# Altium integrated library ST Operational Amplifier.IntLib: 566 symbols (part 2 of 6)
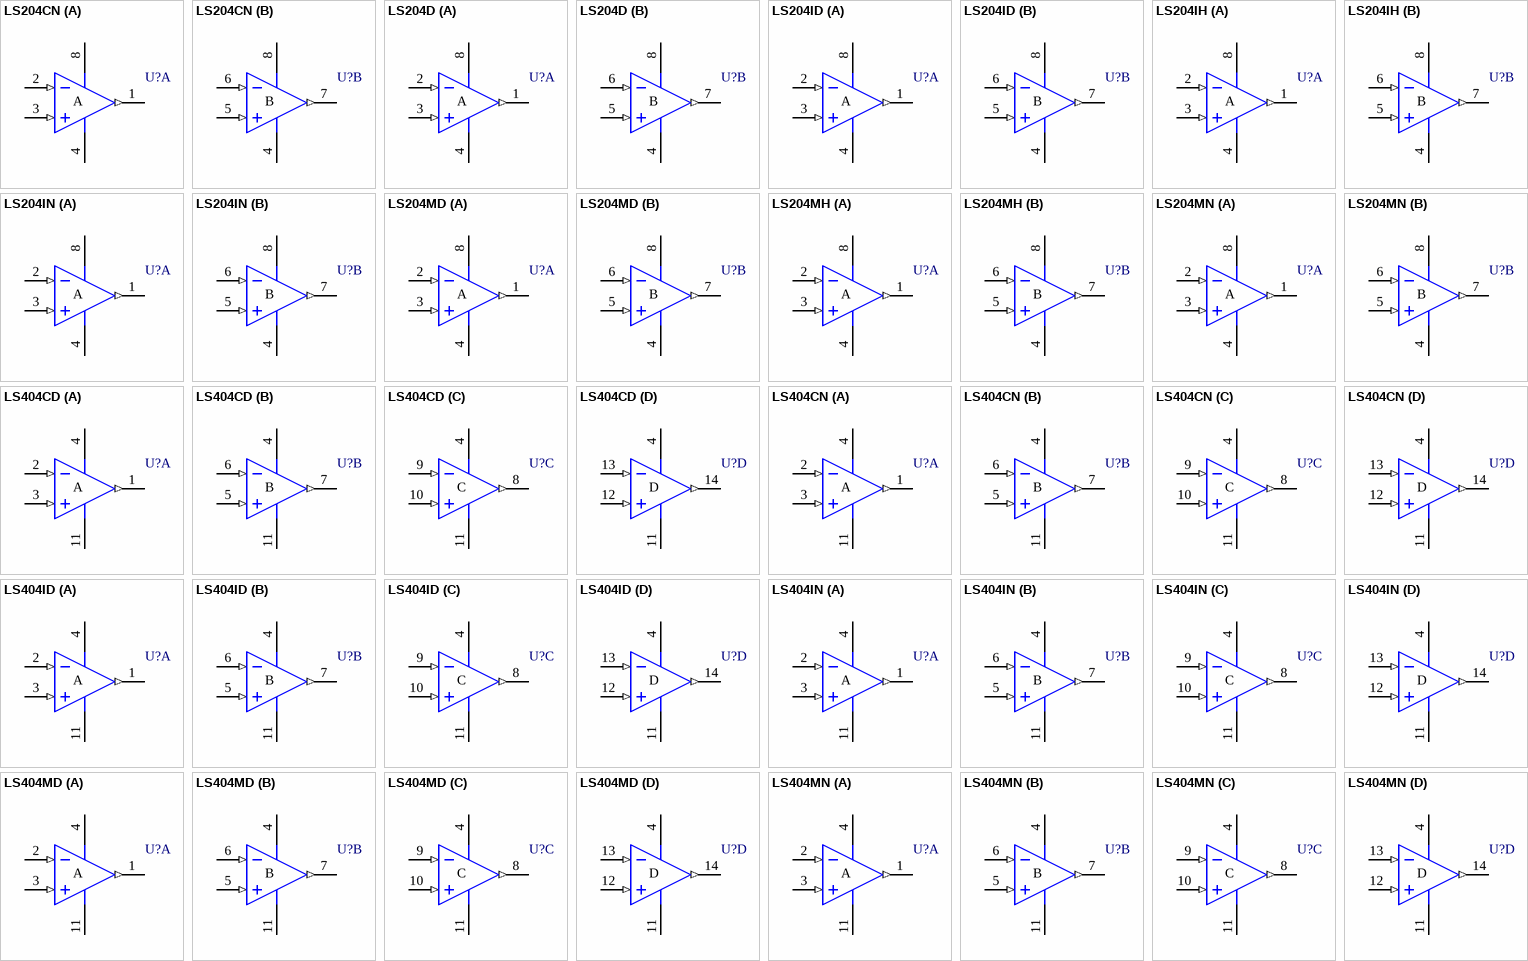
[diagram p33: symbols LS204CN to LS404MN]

## LS404MN
designator U?
High-Performance Quad Operational Amplifier
footprint DIP14 (DIP; 14 Leads; Row Spacing 7.62 mm; Pitch 2.54 mm)
3D model DIP14 (DIP; 14 Leads; Row Spacing 7.62 mm; Pitch 2.54 mm)
pins on every part: 4 V+ (power), 11 V- (power)
part A pins: 1 OUT (out), 2 IN- (in), 3 IN+ (in)
part B pins: 5 IN+ (in), 6 IN- (in), 7 OUT (out)
part C pins: 8 OUT (out), 9 IN- (in), 10 IN+ (in)
part D pins: 12 IN+ (in), 13 IN- (in), 14 OUT (out)

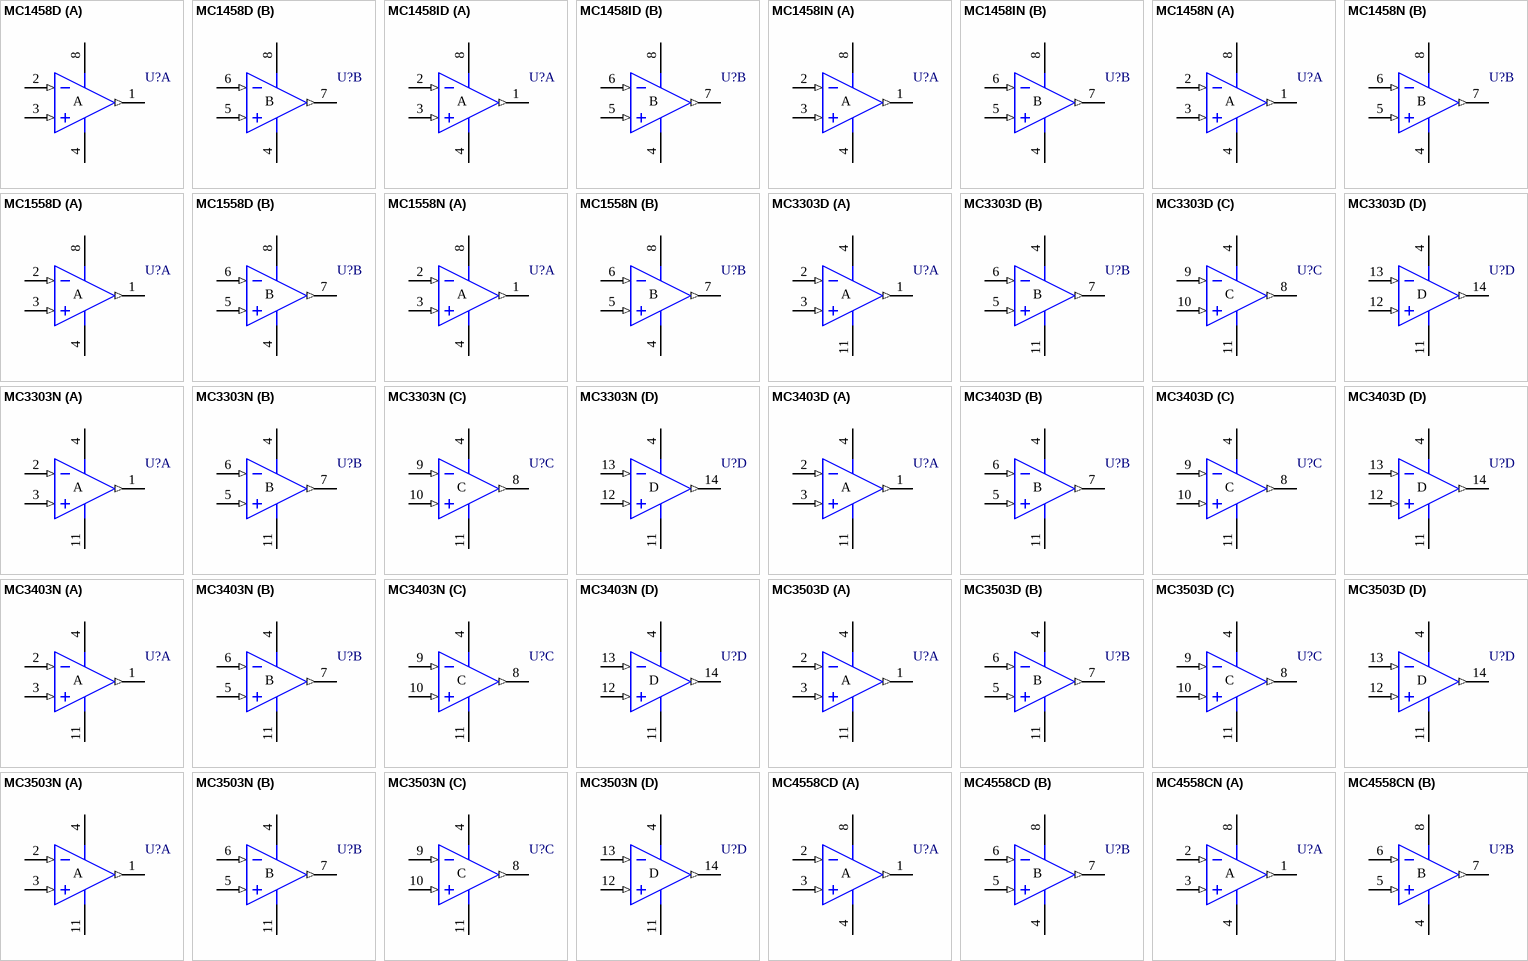
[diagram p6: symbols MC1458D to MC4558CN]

## MC1458D
designator U?
Dual Operational Amplifier
footprint SO8_N (SOIC, 8-Leads, Body 4.9x3.9mm, Pitch 1.27mm, IPC Medium Density)
footprint SO8_L (SOIC, 8-Leads, Body 4.9x3.9mm, Pitch 1.27mm, IPC High Density)
footprint SO8_M (SOIC, 8-Leads, Body 4.9x3.9mm, Pitch 1.27mm, IPC Low Density)
3D model SO8 (8-Pin Small Outline Integrated Circuit 1.27 mm Pitch)
pins on every part: 4 V- (power), 8 V+ (power)
part A pins: 1 OUT (out), 2 IN- (in), 3 IN+ (in)
part B pins: 5 IN+ (in), 6 IN- (in), 7 OUT (out)

## MC1458ID
designator U?
Dual Operational Amplifier
footprint SO8_N (SOIC, 8-Leads, Body 4.9x3.9mm, Pitch 1.27mm, IPC Medium Density)
footprint SO8_L (SOIC, 8-Leads, Body 4.9x3.9mm, Pitch 1.27mm, IPC High Density)
footprint SO8_M (SOIC, 8-Leads, Body 4.9x3.9mm, Pitch 1.27mm, IPC Low Density)
3D model SO8 (8-Pin Small Outline Integrated Circuit 1.27 mm Pitch)
pins on every part: 4 V- (power), 8 V+ (power)
part A pins: 1 OUT (out), 2 IN- (in), 3 IN+ (in)
part B pins: 5 IN+ (in), 6 IN- (in), 7 OUT (out)

## MC1458IN
designator U?
Dual Operational Amplifier
footprint DIP8 (DIP; 8 Leads; Row Spacing 7.62 mm; Pitch 2.54 mm)
3D model DIP8 (DIP; 8 Leads; Row Spacing 7.62 mm; Pitch 2.54 mm)
pins on every part: 4 V- (power), 8 V+ (power)
part A pins: 1 OUT (out), 2 IN- (in), 3 IN+ (in)
part B pins: 5 IN+ (in), 6 IN- (in), 7 OUT (out)

## MC1458N
designator U?
Dual Operational Amplifier
footprint DIP8 (DIP; 8 Leads; Row Spacing 7.62 mm; Pitch 2.54 mm)
3D model DIP8 (DIP; 8 Leads; Row Spacing 7.62 mm; Pitch 2.54 mm)
pins on every part: 4 V- (power), 8 V+ (power)
part A pins: 1 OUT (out), 2 IN- (in), 3 IN+ (in)
part B pins: 5 IN+ (in), 6 IN- (in), 7 OUT (out)

## MC1558D
designator U?
Dual Operational Amplifier
footprint SO8_N (SOIC, 8-Leads, Body 4.9x3.9mm, Pitch 1.27mm, IPC Medium Density)
footprint SO8_L (SOIC, 8-Leads, Body 4.9x3.9mm, Pitch 1.27mm, IPC High Density)
footprint SO8_M (SOIC, 8-Leads, Body 4.9x3.9mm, Pitch 1.27mm, IPC Low Density)
3D model SO8 (8-Pin Small Outline Integrated Circuit 1.27 mm Pitch)
pins on every part: 4 V- (power), 8 V+ (power)
part A pins: 1 OUT (out), 2 IN- (in), 3 IN+ (in)
part B pins: 5 IN+ (in), 6 IN- (in), 7 OUT (out)

## MC1558N
designator U?
Dual Operational Amplifier
footprint DIP8 (DIP; 8 Leads; Row Spacing 7.62 mm; Pitch 2.54 mm)
3D model DIP8 (DIP; 8 Leads; Row Spacing 7.62 mm; Pitch 2.54 mm)
pins on every part: 4 V- (power), 8 V+ (power)
part A pins: 1 OUT (out), 2 IN- (in), 3 IN+ (in)
part B pins: 5 IN+ (in), 6 IN- (in), 7 OUT (out)

## MC3303D
designator U?
Low-Power Quad Bipolar Operational Amplifier
footprint SO14_N (SOIC, 14-Leads, Body 8.7x3.9mm, Pitch 1.27mm, IPC Medium Density)
footprint SO14_L (SOIC, 14-Leads, Body 8.7x3.9mm, Pitch 1.27mm, IPC High Density)
footprint SO14_M (SOIC, 14-Leads, Body 8.7x3.9mm, Pitch 1.27mm, IPC Low Density)
3D model SO14 (14-Pin Small Outline Integrated Circuit 1.27 mm Pitch)
pins on every part: 4 V+ (power), 11 V- (power)
part A pins: 1 OUT (out), 2 IN- (in), 3 IN+ (in)
part B pins: 5 IN+ (in), 6 IN- (in), 7 OUT (out)
part C pins: 8 OUT (out), 9 IN- (in), 10 IN+ (in)
part D pins: 12 IN+ (in), 13 IN- (in), 14 OUT (out)

## MC3303N
designator U?
Low-Power Quad Bipolar Operational Amplifier
footprint DIP14 (DIP; 14 Leads; Row Spacing 7.62 mm; Pitch 2.54 mm)
3D model DIP14 (DIP; 14 Leads; Row Spacing 7.62 mm; Pitch 2.54 mm)
pins on every part: 4 V+ (power), 11 V- (power)
part A pins: 1 OUT (out), 2 IN- (in), 3 IN+ (in)
part B pins: 5 IN+ (in), 6 IN- (in), 7 OUT (out)
part C pins: 8 OUT (out), 9 IN- (in), 10 IN+ (in)
part D pins: 12 IN+ (in), 13 IN- (in), 14 OUT (out)

## MC3403D
designator U?
Low-Power Quad Bipolar Operational Amplifier
footprint SO14_N (SOIC, 14-Leads, Body 8.7x3.9mm, Pitch 1.27mm, IPC Medium Density)
footprint SO14_L (SOIC, 14-Leads, Body 8.7x3.9mm, Pitch 1.27mm, IPC High Density)
footprint SO14_M (SOIC, 14-Leads, Body 8.7x3.9mm, Pitch 1.27mm, IPC Low Density)
3D model SO14 (14-Pin Small Outline Integrated Circuit 1.27 mm Pitch)
simulation model MC3403 (SUBCKT)
pins on every part: 4 V+ (power), 11 V- (power)
part A pins: 1 OUT (out), 2 IN- (in), 3 IN+ (in)
part B pins: 5 IN+ (in), 6 IN- (in), 7 OUT (out)
part C pins: 8 OUT (out), 9 IN- (in), 10 IN+ (in)
part D pins: 12 IN+ (in), 13 IN- (in), 14 OUT (out)

## MC3403N
designator U?
Low-Power Quad Bipolar Operational Amplifier
footprint DIP14 (DIP; 14 Leads; Row Spacing 7.62 mm; Pitch 2.54 mm)
3D model DIP14 (DIP; 14 Leads; Row Spacing 7.62 mm; Pitch 2.54 mm)
simulation model MC3403 (SUBCKT)
pins on every part: 4 V+ (power), 11 V- (power)
part A pins: 1 OUT (out), 2 IN- (in), 3 IN+ (in)
part B pins: 5 IN+ (in), 6 IN- (in), 7 OUT (out)
part C pins: 8 OUT (out), 9 IN- (in), 10 IN+ (in)
part D pins: 12 IN+ (in), 13 IN- (in), 14 OUT (out)

## MC3503D
designator U?
Low-Power Quad Bipolar Operational Amplifier
footprint SO14_N (SOIC, 14-Leads, Body 8.7x3.9mm, Pitch 1.27mm, IPC Medium Density)
footprint SO14_L (SOIC, 14-Leads, Body 8.7x3.9mm, Pitch 1.27mm, IPC High Density)
footprint SO14_M (SOIC, 14-Leads, Body 8.7x3.9mm, Pitch 1.27mm, IPC Low Density)
3D model SO14 (14-Pin Small Outline Integrated Circuit 1.27 mm Pitch)
pins on every part: 4 V+ (power), 11 V- (power)
part A pins: 1 OUT (out), 2 IN- (in), 3 IN+ (in)
part B pins: 5 IN+ (in), 6 IN- (in), 7 OUT (out)
part C pins: 8 OUT (out), 9 IN- (in), 10 IN+ (in)
part D pins: 12 IN+ (in), 13 IN- (in), 14 OUT (out)

## MC3503N
designator U?
Low-Power Quad Bipolar Operational Amplifier
footprint DIP14 (DIP; 14 Leads; Row Spacing 7.62 mm; Pitch 2.54 mm)
3D model DIP14 (DIP; 14 Leads; Row Spacing 7.62 mm; Pitch 2.54 mm)
pins on every part: 4 V+ (power), 11 V- (power)
part A pins: 1 OUT (out), 2 IN- (in), 3 IN+ (in)
part B pins: 5 IN+ (in), 6 IN- (in), 7 OUT (out)
part C pins: 8 OUT (out), 9 IN- (in), 10 IN+ (in)
part D pins: 12 IN+ (in), 13 IN- (in), 14 OUT (out)

## MC4558CD
designator U?
Wide-Bandwidth Dual Bipolar Operational Amplifier
footprint SO8_N (SOIC, 8-Leads, Body 4.9x3.9mm, Pitch 1.27mm, IPC Medium Density)
footprint SO8_L (SOIC, 8-Leads, Body 4.9x3.9mm, Pitch 1.27mm, IPC High Density)
footprint SO8_M (SOIC, 8-Leads, Body 4.9x3.9mm, Pitch 1.27mm, IPC Low Density)
3D model SO8 (8-Pin Small Outline Integrated Circuit 1.27 mm Pitch)
simulation model MC4558 (SUBCKT)
pins on every part: 4 V- (power), 8 V+ (power)
part A pins: 1 OUT (out), 2 IN- (in), 3 IN+ (in)
part B pins: 5 IN+ (in), 6 IN- (in), 7 OUT (out)

## MC4558CN
designator U?
Wide-Bandwidth Dual Bipolar Operational Amplifier
footprint DIP8 (DIP; 8 Leads; Row Spacing 7.62 mm; Pitch 2.54 mm)
3D model DIP8 (DIP; 8 Leads; Row Spacing 7.62 mm; Pitch 2.54 mm)
simulation model MC4558 (SUBCKT)
pins on every part: 4 V- (power), 8 V+ (power)
part A pins: 1 OUT (out), 2 IN- (in), 3 IN+ (in)
part B pins: 5 IN+ (in), 6 IN- (in), 7 OUT (out)

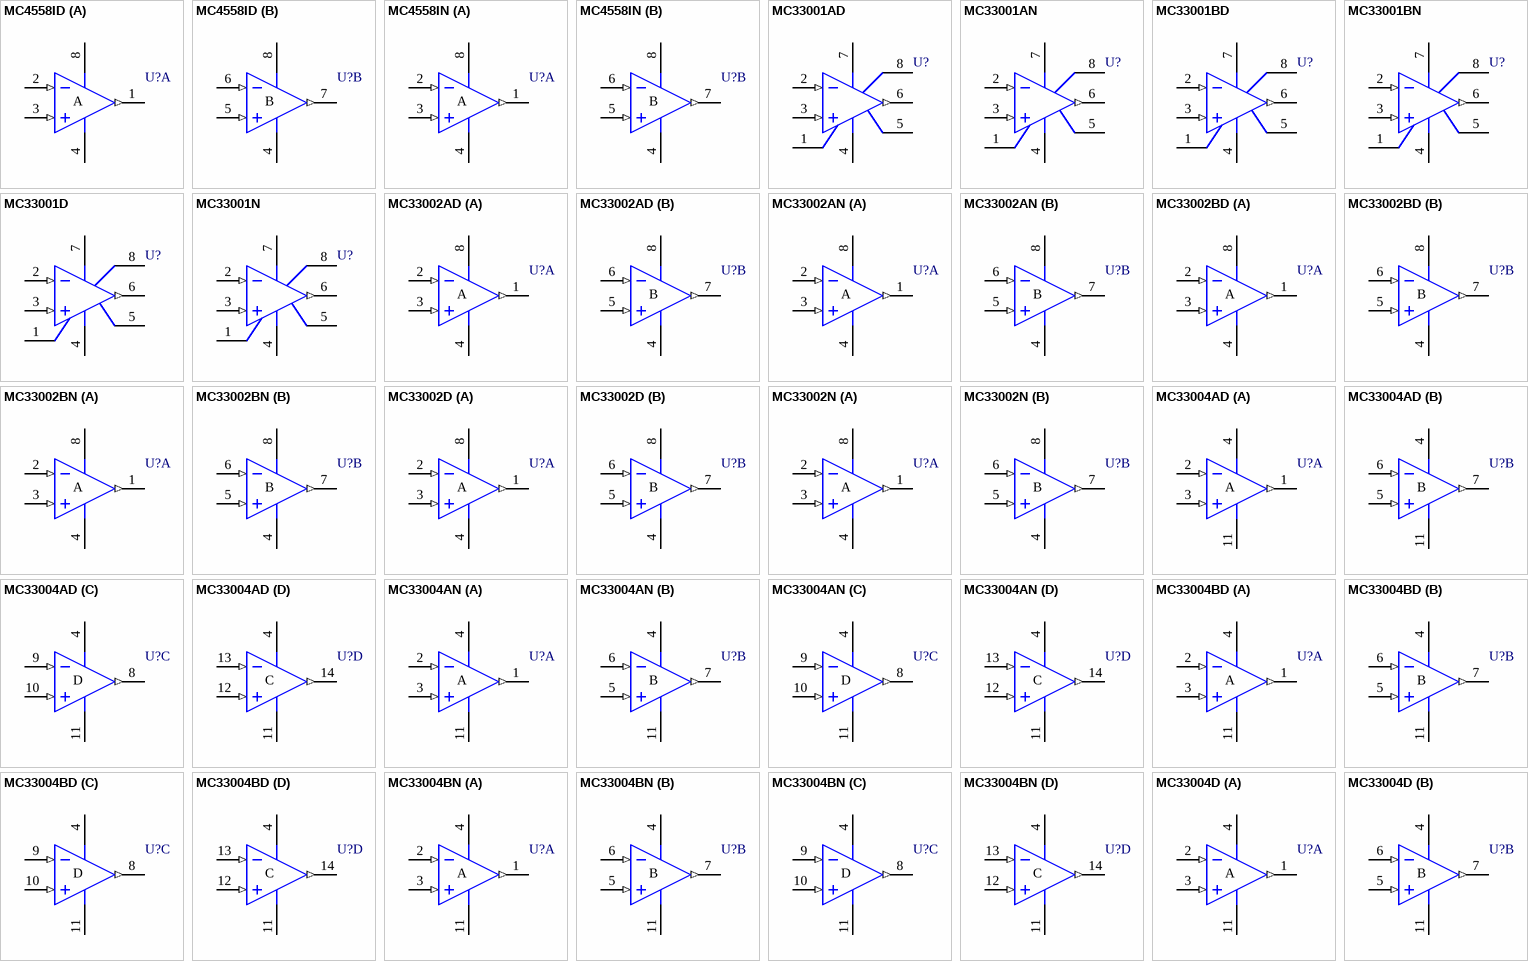
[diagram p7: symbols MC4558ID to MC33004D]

## MC4558ID
designator U?
Wide-Bandwidth Dual Bipolar Operational Amplifier
footprint SO8_N (SOIC, 8-Leads, Body 4.9x3.9mm, Pitch 1.27mm, IPC Medium Density)
footprint SO8_L (SOIC, 8-Leads, Body 4.9x3.9mm, Pitch 1.27mm, IPC High Density)
footprint SO8_M (SOIC, 8-Leads, Body 4.9x3.9mm, Pitch 1.27mm, IPC Low Density)
3D model SO8 (8-Pin Small Outline Integrated Circuit 1.27 mm Pitch)
simulation model MC4558 (SUBCKT)
pins on every part: 4 V- (power), 8 V+ (power)
part A pins: 1 OUT (out), 2 IN- (in), 3 IN+ (in)
part B pins: 5 IN+ (in), 6 IN- (in), 7 OUT (out)

## MC4558IN
designator U?
Wide-Bandwidth Dual Bipolar Operational Amplifier
footprint DIP8 (DIP; 8 Leads; Row Spacing 7.62 mm; Pitch 2.54 mm)
3D model DIP8 (DIP; 8 Leads; Row Spacing 7.62 mm; Pitch 2.54 mm)
simulation model MC4558 (SUBCKT)
pins on every part: 4 V- (power), 8 V+ (power)
part A pins: 1 OUT (out), 2 IN- (in), 3 IN+ (in)
part B pins: 5 IN+ (in), 6 IN- (in), 7 OUT (out)

## MC33001AD
designator U?
General-Purpose Single J-FET Operational Amplifier
footprint SO8_N (SOIC, 8-Leads, Body 4.9x3.9mm, Pitch 1.27mm, IPC Medium Density)
footprint SO8_L (SOIC, 8-Leads, Body 4.9x3.9mm, Pitch 1.27mm, IPC High Density)
footprint SO8_M (SOIC, 8-Leads, Body 4.9x3.9mm, Pitch 1.27mm, IPC Low Density)
3D model SO8 (8-Pin Small Outline Integrated Circuit 1.27 mm Pitch)
pins: 1 OS NULL, 2 IN- (in), 3 IN+ (in), 4 V- (power), 5 OS NULL, 6 OUT (out), 7 V+ (power), 8 NC

## MC33001AN
designator U?
General-Purpose Single J-FET Operational Amplifier
footprint DIP8 (DIP; 8 Leads; Row Spacing 7.62 mm; Pitch 2.54 mm)
3D model DIP8 (DIP; 8 Leads; Row Spacing 7.62 mm; Pitch 2.54 mm)
pins: 1 OS NULL, 2 IN- (in), 3 IN+ (in), 4 V- (power), 5 OS NULL, 6 OUT (out), 7 V+ (power), 8 NC

## MC33001BD
designator U?
General-Purpose Single J-FET Operational Amplifier
footprint SO8_N (SOIC, 8-Leads, Body 4.9x3.9mm, Pitch 1.27mm, IPC Medium Density)
footprint SO8_L (SOIC, 8-Leads, Body 4.9x3.9mm, Pitch 1.27mm, IPC High Density)
footprint SO8_M (SOIC, 8-Leads, Body 4.9x3.9mm, Pitch 1.27mm, IPC Low Density)
3D model SO8 (8-Pin Small Outline Integrated Circuit 1.27 mm Pitch)
pins: 1 OS NULL, 2 IN- (in), 3 IN+ (in), 4 V- (power), 5 OS NULL, 6 OUT (out), 7 V+ (power), 8 NC

## MC33001BN
designator U?
General-Purpose Single J-FET Operational Amplifier
footprint DIP8 (DIP; 8 Leads; Row Spacing 7.62 mm; Pitch 2.54 mm)
3D model DIP8 (DIP; 8 Leads; Row Spacing 7.62 mm; Pitch 2.54 mm)
pins: 1 OS NULL, 2 IN- (in), 3 IN+ (in), 4 V- (power), 5 OS NULL, 6 OUT (out), 7 V+ (power), 8 NC

## MC33001D
designator U?
General-Purpose Single J-FET Operational Amplifier
footprint SO8_N (SOIC, 8-Leads, Body 4.9x3.9mm, Pitch 1.27mm, IPC Medium Density)
footprint SO8_L (SOIC, 8-Leads, Body 4.9x3.9mm, Pitch 1.27mm, IPC High Density)
footprint SO8_M (SOIC, 8-Leads, Body 4.9x3.9mm, Pitch 1.27mm, IPC Low Density)
3D model SO8 (8-Pin Small Outline Integrated Circuit 1.27 mm Pitch)
pins: 1 OS NULL, 2 IN- (in), 3 IN+ (in), 4 V- (power), 5 OS NULL, 6 OUT (out), 7 V+ (power), 8 NC

## MC33001N
designator U?
General-Purpose Single J-FET Operational Amplifier
footprint DIP8 (DIP; 8 Leads; Row Spacing 7.62 mm; Pitch 2.54 mm)
3D model DIP8 (DIP; 8 Leads; Row Spacing 7.62 mm; Pitch 2.54 mm)
pins: 1 OS NULL, 2 IN- (in), 3 IN+ (in), 4 V- (power), 5 OS NULL, 6 OUT (out), 7 V+ (power), 8 NC

## MC33002AD
designator U?
General-Purpose Dual J-FET Operational Amplifier
footprint SO8_N (SOIC, 8-Leads, Body 4.9x3.9mm, Pitch 1.27mm, IPC Medium Density)
footprint SO8_L (SOIC, 8-Leads, Body 4.9x3.9mm, Pitch 1.27mm, IPC High Density)
footprint SO8_M (SOIC, 8-Leads, Body 4.9x3.9mm, Pitch 1.27mm, IPC Low Density)
3D model SO8 (8-Pin Small Outline Integrated Circuit 1.27 mm Pitch)
pins on every part: 4 V- (power), 8 V+ (power)
part A pins: 1 OUT (out), 2 IN- (in), 3 IN+ (in)
part B pins: 5 IN+ (in), 6 IN- (in), 7 OUT (out)

## MC33002AN
designator U?
General-Purpose Dual J-FET Operational Amplifier
footprint DIP8 (DIP; 8 Leads; Row Spacing 7.62 mm; Pitch 2.54 mm)
3D model DIP8 (DIP; 8 Leads; Row Spacing 7.62 mm; Pitch 2.54 mm)
pins on every part: 4 V- (power), 8 V+ (power)
part A pins: 1 OUT (out), 2 IN- (in), 3 IN+ (in)
part B pins: 5 IN+ (in), 6 IN- (in), 7 OUT (out)

## MC33002BD
designator U?
General-Purpose Dual J-FET Operational Amplifier
footprint SO8_N (SOIC, 8-Leads, Body 4.9x3.9mm, Pitch 1.27mm, IPC Medium Density)
footprint SO8_L (SOIC, 8-Leads, Body 4.9x3.9mm, Pitch 1.27mm, IPC High Density)
footprint SO8_M (SOIC, 8-Leads, Body 4.9x3.9mm, Pitch 1.27mm, IPC Low Density)
3D model SO8 (8-Pin Small Outline Integrated Circuit 1.27 mm Pitch)
pins on every part: 4 V- (power), 8 V+ (power)
part A pins: 1 OUT (out), 2 IN- (in), 3 IN+ (in)
part B pins: 5 IN+ (in), 6 IN- (in), 7 OUT (out)

## MC33002BN
designator U?
General-Purpose Dual J-FET Operational Amplifier
footprint DIP8 (DIP; 8 Leads; Row Spacing 7.62 mm; Pitch 2.54 mm)
3D model DIP8 (DIP; 8 Leads; Row Spacing 7.62 mm; Pitch 2.54 mm)
pins on every part: 4 V- (power), 8 V+ (power)
part A pins: 1 OUT (out), 2 IN- (in), 3 IN+ (in)
part B pins: 5 IN+ (in), 6 IN- (in), 7 OUT (out)

## MC33002D
designator U?
General-Purpose Dual J-FET Operational Amplifier
footprint SO8_N (SOIC, 8-Leads, Body 4.9x3.9mm, Pitch 1.27mm, IPC Medium Density)
footprint SO8_L (SOIC, 8-Leads, Body 4.9x3.9mm, Pitch 1.27mm, IPC High Density)
footprint SO8_M (SOIC, 8-Leads, Body 4.9x3.9mm, Pitch 1.27mm, IPC Low Density)
3D model SO8 (8-Pin Small Outline Integrated Circuit 1.27 mm Pitch)
pins on every part: 4 V- (power), 8 V+ (power)
part A pins: 1 OUT (out), 2 IN- (in), 3 IN+ (in)
part B pins: 5 IN+ (in), 6 IN- (in), 7 OUT (out)

## MC33002N
designator U?
General-Purpose Dual J-FET Operational Amplifier
footprint DIP8 (DIP; 8 Leads; Row Spacing 7.62 mm; Pitch 2.54 mm)
3D model DIP8 (DIP; 8 Leads; Row Spacing 7.62 mm; Pitch 2.54 mm)
pins on every part: 4 V- (power), 8 V+ (power)
part A pins: 1 OUT (out), 2 IN- (in), 3 IN+ (in)
part B pins: 5 IN+ (in), 6 IN- (in), 7 OUT (out)

## MC33004AD
designator U?
General-Purpose Quad J-FET Operational Amplifier
footprint SO14_N (SOIC, 14-Leads, Body 8.7x3.9mm, Pitch 1.27mm, IPC Medium Density)
footprint SO14_L (SOIC, 14-Leads, Body 8.7x3.9mm, Pitch 1.27mm, IPC High Density)
footprint SO14_M (SOIC, 14-Leads, Body 8.7x3.9mm, Pitch 1.27mm, IPC Low Density)
3D model SO14 (14-Pin Small Outline Integrated Circuit 1.27 mm Pitch)
pins on every part: 4 V+ (power), 11 V- (power)
part A pins: 1 OUT (out), 2 IN- (in), 3 IN+ (in)
part B pins: 5 IN+ (in), 6 IN- (in), 7 OUT (out)
part C pins: 8 OUT (out), 9 IN- (in), 10 IN+ (in)
part D pins: 12 IN+ (in), 13 IN- (in), 14 OUT (out)

## MC33004AN
designator U?
General-Purpose Quad J-FET Operational Amplifier
footprint DIP14 (DIP; 14 Leads; Row Spacing 7.62 mm; Pitch 2.54 mm)
3D model DIP14 (DIP; 14 Leads; Row Spacing 7.62 mm; Pitch 2.54 mm)
pins on every part: 4 V+ (power), 11 V- (power)
part A pins: 1 OUT (out), 2 IN- (in), 3 IN+ (in)
part B pins: 5 IN+ (in), 6 IN- (in), 7 OUT (out)
part C pins: 8 OUT (out), 9 IN- (in), 10 IN+ (in)
part D pins: 12 IN+ (in), 13 IN- (in), 14 OUT (out)

## MC33004BD
designator U?
General-Purpose Quad J-FET Operational Amplifier
footprint SO14_N (SOIC, 14-Leads, Body 8.7x3.9mm, Pitch 1.27mm, IPC Medium Density)
footprint SO14_L (SOIC, 14-Leads, Body 8.7x3.9mm, Pitch 1.27mm, IPC High Density)
footprint SO14_M (SOIC, 14-Leads, Body 8.7x3.9mm, Pitch 1.27mm, IPC Low Density)
3D model SO14 (14-Pin Small Outline Integrated Circuit 1.27 mm Pitch)
pins on every part: 4 V+ (power), 11 V- (power)
part A pins: 1 OUT (out), 2 IN- (in), 3 IN+ (in)
part B pins: 5 IN+ (in), 6 IN- (in), 7 OUT (out)
part C pins: 8 OUT (out), 9 IN- (in), 10 IN+ (in)
part D pins: 12 IN+ (in), 13 IN- (in), 14 OUT (out)

## MC33004BN
designator U?
General-Purpose Quad J-FET Operational Amplifier
footprint DIP14 (DIP; 14 Leads; Row Spacing 7.62 mm; Pitch 2.54 mm)
3D model DIP14 (DIP; 14 Leads; Row Spacing 7.62 mm; Pitch 2.54 mm)
pins on every part: 4 V+ (power), 11 V- (power)
part A pins: 1 OUT (out), 2 IN- (in), 3 IN+ (in)
part B pins: 5 IN+ (in), 6 IN- (in), 7 OUT (out)
part C pins: 8 OUT (out), 9 IN- (in), 10 IN+ (in)
part D pins: 12 IN+ (in), 13 IN- (in), 14 OUT (out)

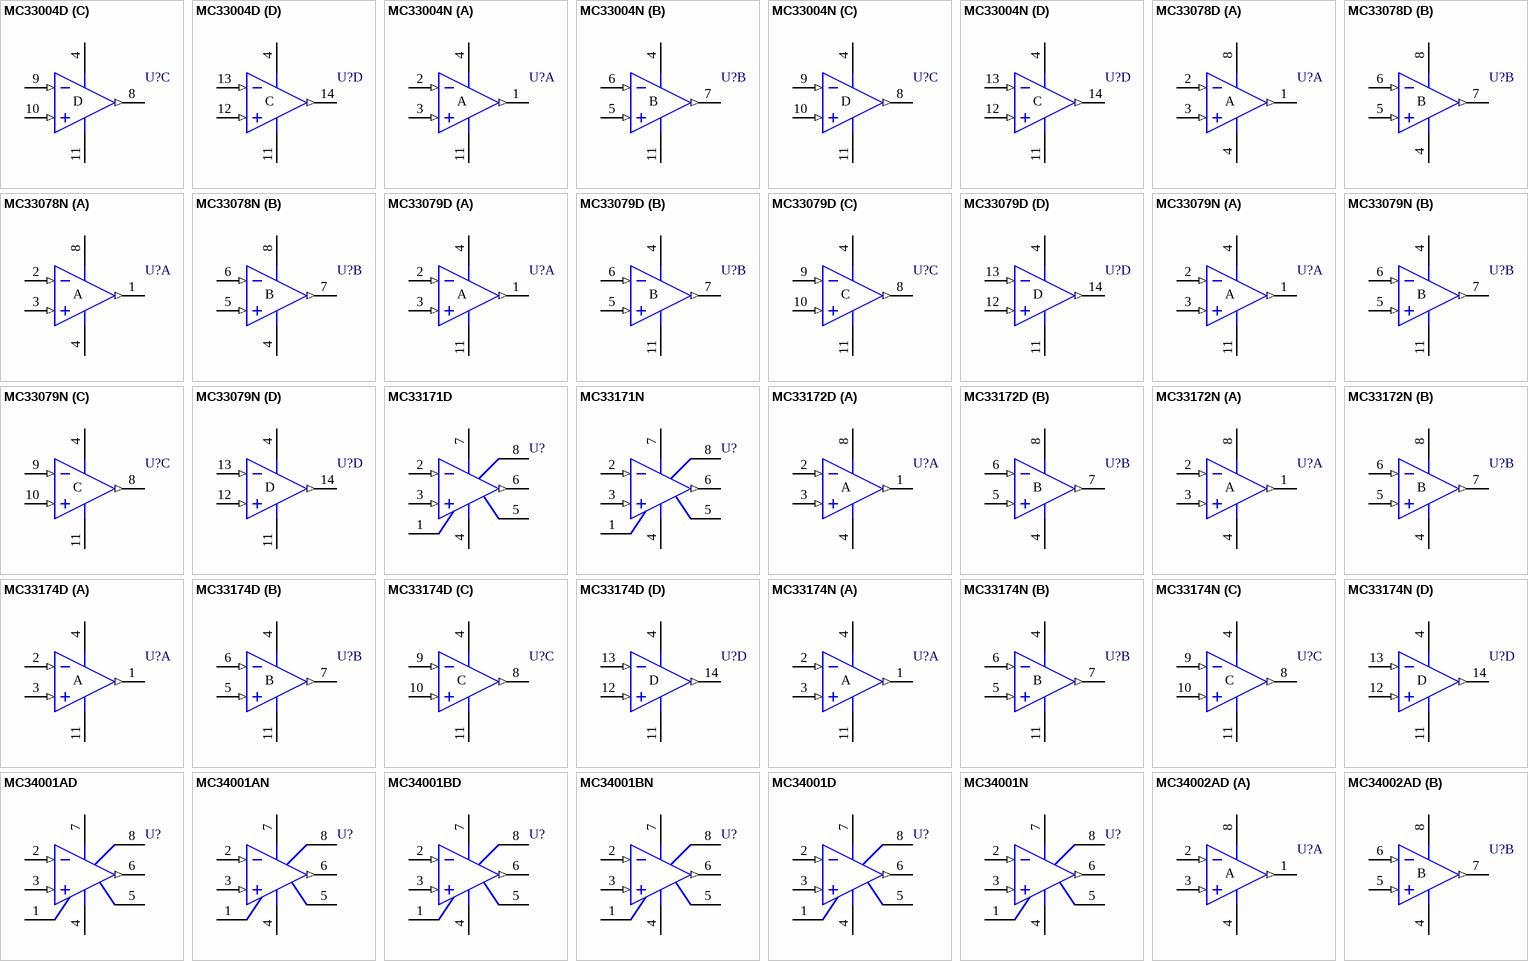
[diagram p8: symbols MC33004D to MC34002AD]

## MC33004D
designator U?
General-Purpose Quad J-FET Operational Amplifier
footprint SO14_N (SOIC, 14-Leads, Body 8.7x3.9mm, Pitch 1.27mm, IPC Medium Density)
footprint SO14_L (SOIC, 14-Leads, Body 8.7x3.9mm, Pitch 1.27mm, IPC High Density)
footprint SO14_M (SOIC, 14-Leads, Body 8.7x3.9mm, Pitch 1.27mm, IPC Low Density)
3D model SO14 (14-Pin Small Outline Integrated Circuit 1.27 mm Pitch)
pins on every part: 4 V+ (power), 11 V- (power)
part A pins: 1 OUT (out), 2 IN- (in), 3 IN+ (in)
part B pins: 5 IN+ (in), 6 IN- (in), 7 OUT (out)
part C pins: 8 OUT (out), 9 IN- (in), 10 IN+ (in)
part D pins: 12 IN+ (in), 13 IN- (in), 14 OUT (out)

## MC33004N
designator U?
General-Purpose Quad J-FET Operational Amplifier
footprint DIP14 (DIP; 14 Leads; Row Spacing 7.62 mm; Pitch 2.54 mm)
3D model DIP14 (DIP; 14 Leads; Row Spacing 7.62 mm; Pitch 2.54 mm)
pins on every part: 4 V+ (power), 11 V- (power)
part A pins: 1 OUT (out), 2 IN- (in), 3 IN+ (in)
part B pins: 5 IN+ (in), 6 IN- (in), 7 OUT (out)
part C pins: 8 OUT (out), 9 IN- (in), 10 IN+ (in)
part D pins: 12 IN+ (in), 13 IN- (in), 14 OUT (out)

## MC33078D
designator U?
Low-Noise Dual Operational Amplifier
footprint SO8_N (SOIC, 8-Leads, Body 4.9x3.9mm, Pitch 1.27mm, IPC Medium Density)
footprint SO8_L (SOIC, 8-Leads, Body 4.9x3.9mm, Pitch 1.27mm, IPC High Density)
footprint SO8_M (SOIC, 8-Leads, Body 4.9x3.9mm, Pitch 1.27mm, IPC Low Density)
3D model SO8 (8-Pin Small Outline Integrated Circuit 1.27 mm Pitch)
simulation model MC33078 (SUBCKT)
pins on every part: 4 V- (power), 8 V+ (power)
part A pins: 1 OUT (out), 2 IN- (in), 3 IN+ (in)
part B pins: 5 IN+ (in), 6 IN- (in), 7 OUT (out)

## MC33078N
designator U?
Low-Noise Dual Operational Amplifier
footprint DIP8 (DIP; 8 Leads; Row Spacing 7.62 mm; Pitch 2.54 mm)
3D model DIP8 (DIP; 8 Leads; Row Spacing 7.62 mm; Pitch 2.54 mm)
simulation model MC33078 (SUBCKT)
pins on every part: 4 V- (power), 8 V+ (power)
part A pins: 1 OUT (out), 2 IN- (in), 3 IN+ (in)
part B pins: 5 IN+ (in), 6 IN- (in), 7 OUT (out)

## MC33079D
designator U?
Low-Noise Quad Operational Amplifier
footprint SO14_N (SOIC, 14-Leads, Body 8.7x3.9mm, Pitch 1.27mm, IPC Medium Density)
footprint SO14_L (SOIC, 14-Leads, Body 8.7x3.9mm, Pitch 1.27mm, IPC High Density)
footprint SO14_M (SOIC, 14-Leads, Body 8.7x3.9mm, Pitch 1.27mm, IPC Low Density)
3D model SO14 (14-Pin Small Outline Integrated Circuit 1.27 mm Pitch)
simulation model MC33079 (SUBCKT)
pins on every part: 4 V+ (power), 11 V- (power)
part A pins: 1 OUT (out), 2 IN- (in), 3 IN+ (in)
part B pins: 5 IN+ (in), 6 IN- (in), 7 OUT (out)
part C pins: 8 OUT (out), 9 IN- (in), 10 IN+ (in)
part D pins: 12 IN+ (in), 13 IN- (in), 14 OUT (out)

## MC33079N
designator U?
Low-Noise Quad Operational Amplifier
footprint DIP14 (DIP; 14 Leads; Row Spacing 7.62 mm; Pitch 2.54 mm)
3D model DIP14 (DIP; 14 Leads; Row Spacing 7.62 mm; Pitch 2.54 mm)
simulation model MC33079 (SUBCKT)
pins on every part: 4 V+ (power), 11 V- (power)
part A pins: 1 OUT (out), 2 IN- (in), 3 IN+ (in)
part B pins: 5 IN+ (in), 6 IN- (in), 7 OUT (out)
part C pins: 8 OUT (out), 9 IN- (in), 10 IN+ (in)
part D pins: 12 IN+ (in), 13 IN- (in), 14 OUT (out)

## MC33171D
designator U?
Low-Power Single Bipolar Operational Amplifier
footprint SO8_N (SOIC, 8-Leads, Body 4.9x3.9mm, Pitch 1.27mm, IPC Medium Density)
footprint SO8_L (SOIC, 8-Leads, Body 4.9x3.9mm, Pitch 1.27mm, IPC High Density)
footprint SO8_M (SOIC, 8-Leads, Body 4.9x3.9mm, Pitch 1.27mm, IPC Low Density)
3D model SO8 (8-Pin Small Outline Integrated Circuit 1.27 mm Pitch)
simulation model MC33171 (SUBCKT)
pins: 1 OS NULL, 2 IN- (in), 3 IN+ (in), 4 V- (power), 5 OS NULL, 6 OUT (out), 7 V+ (power), 8 NC

## MC33171N
designator U?
Low-Power Single Bipolar Operational Amplifier
footprint DIP8 (DIP; 8 Leads; Row Spacing 7.62 mm; Pitch 2.54 mm)
3D model DIP8 (DIP; 8 Leads; Row Spacing 7.62 mm; Pitch 2.54 mm)
simulation model MC33171 (SUBCKT)
pins: 1 OS NULL, 2 IN- (in), 3 IN+ (in), 4 V- (power), 5 OS NULL, 6 OUT (out), 7 V+ (power), 8 NC

## MC33172D
designator U?
Low-Power Dual Bipolar Operational Amplifier
footprint SO8_N (SOIC, 8-Leads, Body 4.9x3.9mm, Pitch 1.27mm, IPC Medium Density)
footprint SO8_L (SOIC, 8-Leads, Body 4.9x3.9mm, Pitch 1.27mm, IPC High Density)
footprint SO8_M (SOIC, 8-Leads, Body 4.9x3.9mm, Pitch 1.27mm, IPC Low Density)
3D model SO8 (8-Pin Small Outline Integrated Circuit 1.27 mm Pitch)
simulation model MC33172 (SUBCKT)
pins on every part: 4 V- (power), 8 V+ (power)
part A pins: 1 OUT (out), 2 IN- (in), 3 IN+ (in)
part B pins: 5 IN+ (in), 6 IN- (in), 7 OUT (out)

## MC33172N
designator U?
Low-Power Dual Bipolar Operational Amplifier
footprint DIP8 (DIP; 8 Leads; Row Spacing 7.62 mm; Pitch 2.54 mm)
3D model DIP8 (DIP; 8 Leads; Row Spacing 7.62 mm; Pitch 2.54 mm)
simulation model MC33172 (SUBCKT)
pins on every part: 4 V- (power), 8 V+ (power)
part A pins: 1 OUT (out), 2 IN- (in), 3 IN+ (in)
part B pins: 5 IN+ (in), 6 IN- (in), 7 OUT (out)

## MC33174D
designator U?
Low-Power Quad Bipolar Operational Amplifier
footprint SO14_N (SOIC, 14-Leads, Body 8.7x3.9mm, Pitch 1.27mm, IPC Medium Density)
footprint SO14_L (SOIC, 14-Leads, Body 8.7x3.9mm, Pitch 1.27mm, IPC High Density)
footprint SO14_M (SOIC, 14-Leads, Body 8.7x3.9mm, Pitch 1.27mm, IPC Low Density)
3D model SO14 (14-Pin Small Outline Integrated Circuit 1.27 mm Pitch)
simulation model MC33174 (SUBCKT)
pins on every part: 4 V+ (power), 11 V- (power)
part A pins: 1 OUT (out), 2 IN- (in), 3 IN+ (in)
part B pins: 5 IN+ (in), 6 IN- (in), 7 OUT (out)
part C pins: 8 OUT (out), 9 IN- (in), 10 IN+ (in)
part D pins: 12 IN+ (in), 13 IN- (in), 14 OUT (out)

## MC33174N
designator U?
Low-Power Quad Bipolar Operational Amplifier
footprint DIP14 (DIP; 14 Leads; Row Spacing 7.62 mm; Pitch 2.54 mm)
3D model DIP14 (DIP; 14 Leads; Row Spacing 7.62 mm; Pitch 2.54 mm)
simulation model MC33174 (SUBCKT)
pins on every part: 4 V+ (power), 11 V- (power)
part A pins: 1 OUT (out), 2 IN- (in), 3 IN+ (in)
part B pins: 5 IN+ (in), 6 IN- (in), 7 OUT (out)
part C pins: 8 OUT (out), 9 IN- (in), 10 IN+ (in)
part D pins: 12 IN+ (in), 13 IN- (in), 14 OUT (out)

## MC34001AD
designator U?
General-Purpose Single J-FET Operational Amplifier
footprint SO8_N (SOIC, 8-Leads, Body 4.9x3.9mm, Pitch 1.27mm, IPC Medium Density)
footprint SO8_L (SOIC, 8-Leads, Body 4.9x3.9mm, Pitch 1.27mm, IPC High Density)
footprint SO8_M (SOIC, 8-Leads, Body 4.9x3.9mm, Pitch 1.27mm, IPC Low Density)
3D model SO8 (8-Pin Small Outline Integrated Circuit 1.27 mm Pitch)
simulation model MC34001 (SUBCKT)
pins: 1 OS NULL, 2 IN- (in), 3 IN+ (in), 4 V- (power), 5 OS NULL, 6 OUT (out), 7 V+ (power), 8 NC

## MC34001AN
designator U?
General-Purpose Single J-FET Operational Amplifier
footprint DIP8 (DIP; 8 Leads; Row Spacing 7.62 mm; Pitch 2.54 mm)
3D model DIP8 (DIP; 8 Leads; Row Spacing 7.62 mm; Pitch 2.54 mm)
simulation model MC34001 (SUBCKT)
pins: 1 OS NULL, 2 IN- (in), 3 IN+ (in), 4 V- (power), 5 OS NULL, 6 OUT (out), 7 V+ (power), 8 NC

## MC34001BD
designator U?
General-Purpose Single J-FET Operational Amplifier
footprint SO8_N (SOIC, 8-Leads, Body 4.9x3.9mm, Pitch 1.27mm, IPC Medium Density)
footprint SO8_L (SOIC, 8-Leads, Body 4.9x3.9mm, Pitch 1.27mm, IPC High Density)
footprint SO8_M (SOIC, 8-Leads, Body 4.9x3.9mm, Pitch 1.27mm, IPC Low Density)
3D model SO8 (8-Pin Small Outline Integrated Circuit 1.27 mm Pitch)
simulation model MC34001 (SUBCKT)
pins: 1 OS NULL, 2 IN- (in), 3 IN+ (in), 4 V- (power), 5 OS NULL, 6 OUT (out), 7 V+ (power), 8 NC

## MC34001BN
designator U?
General-Purpose Single J-FET Operational Amplifier
footprint DIP8 (DIP; 8 Leads; Row Spacing 7.62 mm; Pitch 2.54 mm)
3D model DIP8 (DIP; 8 Leads; Row Spacing 7.62 mm; Pitch 2.54 mm)
simulation model MC34001 (SUBCKT)
pins: 1 OS NULL, 2 IN- (in), 3 IN+ (in), 4 V- (power), 5 OS NULL, 6 OUT (out), 7 V+ (power), 8 NC

## MC34001D
designator U?
General-Purpose Single J-FET Operational Amplifier
footprint SO8_N (SOIC, 8-Leads, Body 4.9x3.9mm, Pitch 1.27mm, IPC Medium Density)
footprint SO8_L (SOIC, 8-Leads, Body 4.9x3.9mm, Pitch 1.27mm, IPC High Density)
footprint SO8_M (SOIC, 8-Leads, Body 4.9x3.9mm, Pitch 1.27mm, IPC Low Density)
3D model SO8 (8-Pin Small Outline Integrated Circuit 1.27 mm Pitch)
simulation model MC34001 (SUBCKT)
pins: 1 OS NULL, 2 IN- (in), 3 IN+ (in), 4 V- (power), 5 OS NULL, 6 OUT (out), 7 V+ (power), 8 NC

## MC34001N
designator U?
General-Purpose Single J-FET Operational Amplifier
footprint DIP8 (DIP; 8 Leads; Row Spacing 7.62 mm; Pitch 2.54 mm)
3D model DIP8 (DIP; 8 Leads; Row Spacing 7.62 mm; Pitch 2.54 mm)
simulation model MC34001 (SUBCKT)
pins: 1 OS NULL, 2 IN- (in), 3 IN+ (in), 4 V- (power), 5 OS NULL, 6 OUT (out), 7 V+ (power), 8 NC

## MC34002AD
designator U?
General-Purpose Dual J-FET Operational Amplifier
footprint SO8_N (SOIC, 8-Leads, Body 4.9x3.9mm, Pitch 1.27mm, IPC Medium Density)
footprint SO8_L (SOIC, 8-Leads, Body 4.9x3.9mm, Pitch 1.27mm, IPC High Density)
footprint SO8_M (SOIC, 8-Leads, Body 4.9x3.9mm, Pitch 1.27mm, IPC Low Density)
3D model SO8 (8-Pin Small Outline Integrated Circuit 1.27 mm Pitch)
pins on every part: 4 V- (power), 8 V+ (power)
part A pins: 1 OUT (out), 2 IN- (in), 3 IN+ (in)
part B pins: 5 IN+ (in), 6 IN- (in), 7 OUT (out)

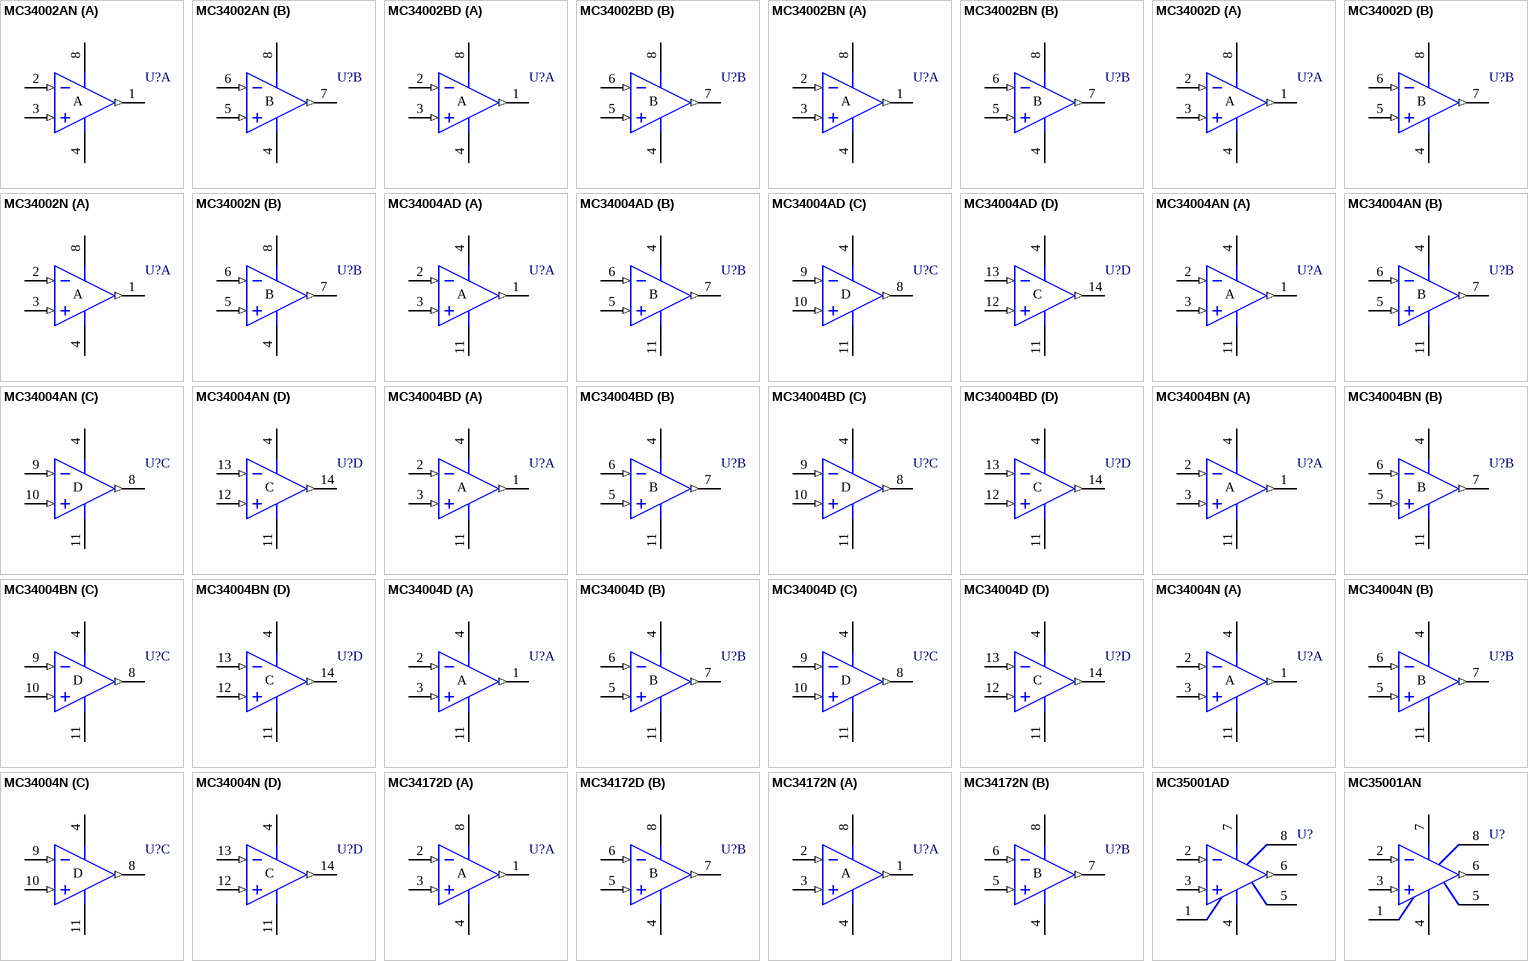
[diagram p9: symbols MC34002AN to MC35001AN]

## MC34002AN
designator U?
General-Purpose Dual J-FET Operational Amplifier
footprint DIP8 (DIP; 8 Leads; Row Spacing 7.62 mm; Pitch 2.54 mm)
3D model DIP8 (DIP; 8 Leads; Row Spacing 7.62 mm; Pitch 2.54 mm)
pins on every part: 4 V- (power), 8 V+ (power)
part A pins: 1 OUT (out), 2 IN- (in), 3 IN+ (in)
part B pins: 5 IN+ (in), 6 IN- (in), 7 OUT (out)

## MC34002BD
designator U?
General-Purpose Dual J-FET Operational Amplifier
footprint SO8_N (SOIC, 8-Leads, Body 4.9x3.9mm, Pitch 1.27mm, IPC Medium Density)
footprint SO8_L (SOIC, 8-Leads, Body 4.9x3.9mm, Pitch 1.27mm, IPC High Density)
footprint SO8_M (SOIC, 8-Leads, Body 4.9x3.9mm, Pitch 1.27mm, IPC Low Density)
3D model SO8 (8-Pin Small Outline Integrated Circuit 1.27 mm Pitch)
pins on every part: 4 V- (power), 8 V+ (power)
part A pins: 1 OUT (out), 2 IN- (in), 3 IN+ (in)
part B pins: 5 IN+ (in), 6 IN- (in), 7 OUT (out)

## MC34002BN
designator U?
General-Purpose Dual J-FET Operational Amplifier
footprint DIP8 (DIP; 8 Leads; Row Spacing 7.62 mm; Pitch 2.54 mm)
3D model DIP8 (DIP; 8 Leads; Row Spacing 7.62 mm; Pitch 2.54 mm)
pins on every part: 4 V- (power), 8 V+ (power)
part A pins: 1 OUT (out), 2 IN- (in), 3 IN+ (in)
part B pins: 5 IN+ (in), 6 IN- (in), 7 OUT (out)

## MC34002D
designator U?
General-Purpose Dual J-FET Operational Amplifier
footprint SO8_N (SOIC, 8-Leads, Body 4.9x3.9mm, Pitch 1.27mm, IPC Medium Density)
footprint SO8_L (SOIC, 8-Leads, Body 4.9x3.9mm, Pitch 1.27mm, IPC High Density)
footprint SO8_M (SOIC, 8-Leads, Body 4.9x3.9mm, Pitch 1.27mm, IPC Low Density)
3D model SO8 (8-Pin Small Outline Integrated Circuit 1.27 mm Pitch)
pins on every part: 4 V- (power), 8 V+ (power)
part A pins: 1 OUT (out), 2 IN- (in), 3 IN+ (in)
part B pins: 5 IN+ (in), 6 IN- (in), 7 OUT (out)

## MC34002N
designator U?
General-Purpose Dual J-FET Operational Amplifier
footprint DIP8 (DIP; 8 Leads; Row Spacing 7.62 mm; Pitch 2.54 mm)
3D model DIP8 (DIP; 8 Leads; Row Spacing 7.62 mm; Pitch 2.54 mm)
pins on every part: 4 V- (power), 8 V+ (power)
part A pins: 1 OUT (out), 2 IN- (in), 3 IN+ (in)
part B pins: 5 IN+ (in), 6 IN- (in), 7 OUT (out)

## MC34004AD
designator U?
General-Purpose Quad J-FET Operational Amplifier
footprint SO14_N (SOIC, 14-Leads, Body 8.7x3.9mm, Pitch 1.27mm, IPC Medium Density)
footprint SO14_L (SOIC, 14-Leads, Body 8.7x3.9mm, Pitch 1.27mm, IPC High Density)
footprint SO14_M (SOIC, 14-Leads, Body 8.7x3.9mm, Pitch 1.27mm, IPC Low Density)
3D model SO14 (14-Pin Small Outline Integrated Circuit 1.27 mm Pitch)
pins on every part: 4 V+ (power), 11 V- (power)
part A pins: 1 OUT (out), 2 IN- (in), 3 IN+ (in)
part B pins: 5 IN+ (in), 6 IN- (in), 7 OUT (out)
part C pins: 8 OUT (out), 9 IN- (in), 10 IN+ (in)
part D pins: 12 IN+ (in), 13 IN- (in), 14 OUT (out)

## MC34004AN
designator U?
General-Purpose Quad J-FET Operational Amplifier
footprint DIP14 (DIP; 14 Leads; Row Spacing 7.62 mm; Pitch 2.54 mm)
3D model DIP14 (DIP; 14 Leads; Row Spacing 7.62 mm; Pitch 2.54 mm)
pins on every part: 4 V+ (power), 11 V- (power)
part A pins: 1 OUT (out), 2 IN- (in), 3 IN+ (in)
part B pins: 5 IN+ (in), 6 IN- (in), 7 OUT (out)
part C pins: 8 OUT (out), 9 IN- (in), 10 IN+ (in)
part D pins: 12 IN+ (in), 13 IN- (in), 14 OUT (out)

## MC34004BD
designator U?
General-Purpose Quad J-FET Operational Amplifier
footprint SO14_N (SOIC, 14-Leads, Body 8.7x3.9mm, Pitch 1.27mm, IPC Medium Density)
footprint SO14_L (SOIC, 14-Leads, Body 8.7x3.9mm, Pitch 1.27mm, IPC High Density)
footprint SO14_M (SOIC, 14-Leads, Body 8.7x3.9mm, Pitch 1.27mm, IPC Low Density)
3D model SO14 (14-Pin Small Outline Integrated Circuit 1.27 mm Pitch)
pins on every part: 4 V+ (power), 11 V- (power)
part A pins: 1 OUT (out), 2 IN- (in), 3 IN+ (in)
part B pins: 5 IN+ (in), 6 IN- (in), 7 OUT (out)
part C pins: 8 OUT (out), 9 IN- (in), 10 IN+ (in)
part D pins: 12 IN+ (in), 13 IN- (in), 14 OUT (out)

## MC34004BN
designator U?
General-Purpose Quad J-FET Operational Amplifier
footprint DIP14 (DIP; 14 Leads; Row Spacing 7.62 mm; Pitch 2.54 mm)
3D model DIP14 (DIP; 14 Leads; Row Spacing 7.62 mm; Pitch 2.54 mm)
pins on every part: 4 V+ (power), 11 V- (power)
part A pins: 1 OUT (out), 2 IN- (in), 3 IN+ (in)
part B pins: 5 IN+ (in), 6 IN- (in), 7 OUT (out)
part C pins: 8 OUT (out), 9 IN- (in), 10 IN+ (in)
part D pins: 12 IN+ (in), 13 IN- (in), 14 OUT (out)

## MC34004D
designator U?
General-Purpose Quad J-FET Operational Amplifier
footprint SO14_N (SOIC, 14-Leads, Body 8.7x3.9mm, Pitch 1.27mm, IPC Medium Density)
footprint SO14_L (SOIC, 14-Leads, Body 8.7x3.9mm, Pitch 1.27mm, IPC High Density)
footprint SO14_M (SOIC, 14-Leads, Body 8.7x3.9mm, Pitch 1.27mm, IPC Low Density)
3D model SO14 (14-Pin Small Outline Integrated Circuit 1.27 mm Pitch)
pins on every part: 4 V+ (power), 11 V- (power)
part A pins: 1 OUT (out), 2 IN- (in), 3 IN+ (in)
part B pins: 5 IN+ (in), 6 IN- (in), 7 OUT (out)
part C pins: 8 OUT (out), 9 IN- (in), 10 IN+ (in)
part D pins: 12 IN+ (in), 13 IN- (in), 14 OUT (out)

## MC34004N
designator U?
General-Purpose Quad J-FET Operational Amplifier
footprint DIP14 (DIP; 14 Leads; Row Spacing 7.62 mm; Pitch 2.54 mm)
3D model DIP14 (DIP; 14 Leads; Row Spacing 7.62 mm; Pitch 2.54 mm)
pins on every part: 4 V+ (power), 11 V- (power)
part A pins: 1 OUT (out), 2 IN- (in), 3 IN+ (in)
part B pins: 5 IN+ (in), 6 IN- (in), 7 OUT (out)
part C pins: 8 OUT (out), 9 IN- (in), 10 IN+ (in)
part D pins: 12 IN+ (in), 13 IN- (in), 14 OUT (out)

## MC34172D
designator U?
Low-Power Dual Bipolar Operational Amplifier
footprint SO8_N (SOIC, 8-Leads, Body 4.9x3.9mm, Pitch 1.27mm, IPC Medium Density)
footprint SO8_L (SOIC, 8-Leads, Body 4.9x3.9mm, Pitch 1.27mm, IPC High Density)
footprint SO8_M (SOIC, 8-Leads, Body 4.9x3.9mm, Pitch 1.27mm, IPC Low Density)
3D model SO8 (8-Pin Small Outline Integrated Circuit 1.27 mm Pitch)
pins on every part: 4 V- (power), 8 V+ (power)
part A pins: 1 OUT (out), 2 IN- (in), 3 IN+ (in)
part B pins: 5 IN+ (in), 6 IN- (in), 7 OUT (out)

## MC34172N
designator U?
Low-Power Dual Bipolar Operational Amplifier
footprint DIP8 (DIP; 8 Leads; Row Spacing 7.62 mm; Pitch 2.54 mm)
3D model DIP8 (DIP; 8 Leads; Row Spacing 7.62 mm; Pitch 2.54 mm)
pins on every part: 4 V- (power), 8 V+ (power)
part A pins: 1 OUT (out), 2 IN- (in), 3 IN+ (in)
part B pins: 5 IN+ (in), 6 IN- (in), 7 OUT (out)

## MC35001AD
designator U?
General-Purpose Single J-FET Operational Amplifier
footprint SO8_N (SOIC, 8-Leads, Body 4.9x3.9mm, Pitch 1.27mm, IPC Medium Density)
footprint SO8_L (SOIC, 8-Leads, Body 4.9x3.9mm, Pitch 1.27mm, IPC High Density)
footprint SO8_M (SOIC, 8-Leads, Body 4.9x3.9mm, Pitch 1.27mm, IPC Low Density)
3D model SO8 (8-Pin Small Outline Integrated Circuit 1.27 mm Pitch)
pins: 1 OS NULL, 2 IN- (in), 3 IN+ (in), 4 V- (power), 5 OS NULL, 6 OUT (out), 7 V+ (power), 8 NC

## MC35001AN
designator U?
General-Purpose Single J-FET Operational Amplifier
footprint DIP8 (DIP; 8 Leads; Row Spacing 7.62 mm; Pitch 2.54 mm)
3D model DIP8 (DIP; 8 Leads; Row Spacing 7.62 mm; Pitch 2.54 mm)
pins: 1 OS NULL, 2 IN- (in), 3 IN+ (in), 4 V- (power), 5 OS NULL, 6 OUT (out), 7 V+ (power), 8 NC

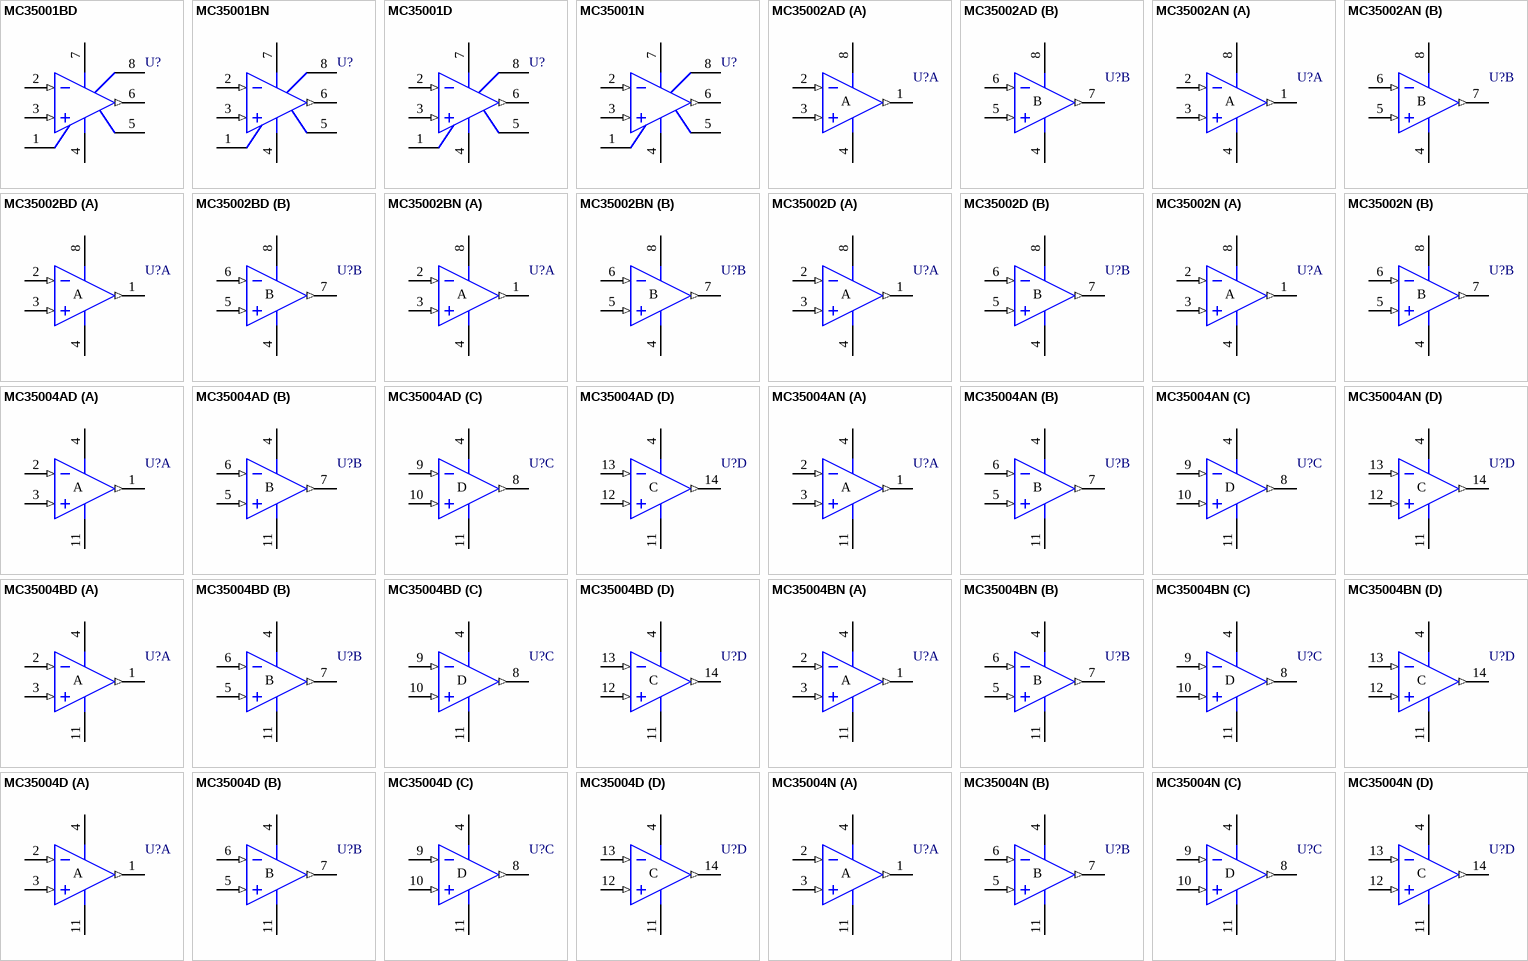
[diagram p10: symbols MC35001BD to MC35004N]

## MC35001BD
designator U?
General-Purpose Single J-FET Operational Amplifier
footprint SO8_N (SOIC, 8-Leads, Body 4.9x3.9mm, Pitch 1.27mm, IPC Medium Density)
footprint SO8_L (SOIC, 8-Leads, Body 4.9x3.9mm, Pitch 1.27mm, IPC High Density)
footprint SO8_M (SOIC, 8-Leads, Body 4.9x3.9mm, Pitch 1.27mm, IPC Low Density)
3D model SO8 (8-Pin Small Outline Integrated Circuit 1.27 mm Pitch)
pins: 1 OS NULL, 2 IN- (in), 3 IN+ (in), 4 V- (power), 5 OS NULL, 6 OUT (out), 7 V+ (power), 8 NC

## MC35001BN
designator U?
General-Purpose Single J-FET Operational Amplifier
footprint DIP8 (DIP; 8 Leads; Row Spacing 7.62 mm; Pitch 2.54 mm)
3D model DIP8 (DIP; 8 Leads; Row Spacing 7.62 mm; Pitch 2.54 mm)
pins: 1 OS NULL, 2 IN- (in), 3 IN+ (in), 4 V- (power), 5 OS NULL, 6 OUT (out), 7 V+ (power), 8 NC

## MC35001D
designator U?
General-Purpose Single J-FET Operational Amplifier
footprint SO8_N (SOIC, 8-Leads, Body 4.9x3.9mm, Pitch 1.27mm, IPC Medium Density)
footprint SO8_L (SOIC, 8-Leads, Body 4.9x3.9mm, Pitch 1.27mm, IPC High Density)
footprint SO8_M (SOIC, 8-Leads, Body 4.9x3.9mm, Pitch 1.27mm, IPC Low Density)
3D model SO8 (8-Pin Small Outline Integrated Circuit 1.27 mm Pitch)
pins: 1 OS NULL, 2 IN- (in), 3 IN+ (in), 4 V- (power), 5 OS NULL, 6 OUT (out), 7 V+ (power), 8 NC

## MC35001N
designator U?
General-Purpose Single J-FET Operational Amplifier
footprint DIP8 (DIP; 8 Leads; Row Spacing 7.62 mm; Pitch 2.54 mm)
3D model DIP8 (DIP; 8 Leads; Row Spacing 7.62 mm; Pitch 2.54 mm)
pins: 1 OS NULL, 2 IN- (in), 3 IN+ (in), 4 V- (power), 5 OS NULL, 6 OUT (out), 7 V+ (power), 8 NC

## MC35002AD
designator U?
General-Purpose Dual J-FET Operational Amplifier
footprint SO8_N (SOIC, 8-Leads, Body 4.9x3.9mm, Pitch 1.27mm, IPC Medium Density)
footprint SO8_L (SOIC, 8-Leads, Body 4.9x3.9mm, Pitch 1.27mm, IPC High Density)
footprint SO8_M (SOIC, 8-Leads, Body 4.9x3.9mm, Pitch 1.27mm, IPC Low Density)
3D model SO8 (8-Pin Small Outline Integrated Circuit 1.27 mm Pitch)
pins on every part: 4 V- (power), 8 V+ (power)
part A pins: 1 OUT (out), 2 IN- (in), 3 IN+ (in)
part B pins: 5 IN+ (in), 6 IN- (in), 7 OUT (out)

## MC35002AN
designator U?
General-Purpose Dual J-FET Operational Amplifier
footprint DIP8 (DIP; 8 Leads; Row Spacing 7.62 mm; Pitch 2.54 mm)
3D model DIP8 (DIP; 8 Leads; Row Spacing 7.62 mm; Pitch 2.54 mm)
pins on every part: 4 V- (power), 8 V+ (power)
part A pins: 1 OUT (out), 2 IN- (in), 3 IN+ (in)
part B pins: 5 IN+ (in), 6 IN- (in), 7 OUT (out)

## MC35002BD
designator U?
General-Purpose Dual J-FET Operational Amplifier
footprint SO8_N (SOIC, 8-Leads, Body 4.9x3.9mm, Pitch 1.27mm, IPC Medium Density)
footprint SO8_L (SOIC, 8-Leads, Body 4.9x3.9mm, Pitch 1.27mm, IPC High Density)
footprint SO8_M (SOIC, 8-Leads, Body 4.9x3.9mm, Pitch 1.27mm, IPC Low Density)
3D model SO8 (8-Pin Small Outline Integrated Circuit 1.27 mm Pitch)
pins on every part: 4 V- (power), 8 V+ (power)
part A pins: 1 OUT (out), 2 IN- (in), 3 IN+ (in)
part B pins: 5 IN+ (in), 6 IN- (in), 7 OUT (out)

## MC35002BN
designator U?
General-Purpose Dual J-FET Operational Amplifier
footprint DIP8 (DIP; 8 Leads; Row Spacing 7.62 mm; Pitch 2.54 mm)
3D model DIP8 (DIP; 8 Leads; Row Spacing 7.62 mm; Pitch 2.54 mm)
pins on every part: 4 V- (power), 8 V+ (power)
part A pins: 1 OUT (out), 2 IN- (in), 3 IN+ (in)
part B pins: 5 IN+ (in), 6 IN- (in), 7 OUT (out)

## MC35002D
designator U?
General-Purpose Dual J-FET Operational Amplifier
footprint SO8_N (SOIC, 8-Leads, Body 4.9x3.9mm, Pitch 1.27mm, IPC Medium Density)
footprint SO8_L (SOIC, 8-Leads, Body 4.9x3.9mm, Pitch 1.27mm, IPC High Density)
footprint SO8_M (SOIC, 8-Leads, Body 4.9x3.9mm, Pitch 1.27mm, IPC Low Density)
3D model SO8 (8-Pin Small Outline Integrated Circuit 1.27 mm Pitch)
pins on every part: 4 V- (power), 8 V+ (power)
part A pins: 1 OUT (out), 2 IN- (in), 3 IN+ (in)
part B pins: 5 IN+ (in), 6 IN- (in), 7 OUT (out)

## MC35002N
designator U?
General-Purpose Dual J-FET Operational Amplifier
footprint DIP8 (DIP; 8 Leads; Row Spacing 7.62 mm; Pitch 2.54 mm)
3D model DIP8 (DIP; 8 Leads; Row Spacing 7.62 mm; Pitch 2.54 mm)
pins on every part: 4 V- (power), 8 V+ (power)
part A pins: 1 OUT (out), 2 IN- (in), 3 IN+ (in)
part B pins: 5 IN+ (in), 6 IN- (in), 7 OUT (out)

## MC35004AD
designator U?
General-Purpose Quad J-FET Operational Amplifier
footprint SO14_N (SOIC, 14-Leads, Body 8.7x3.9mm, Pitch 1.27mm, IPC Medium Density)
footprint SO14_L (SOIC, 14-Leads, Body 8.7x3.9mm, Pitch 1.27mm, IPC High Density)
footprint SO14_M (SOIC, 14-Leads, Body 8.7x3.9mm, Pitch 1.27mm, IPC Low Density)
3D model SO14 (14-Pin Small Outline Integrated Circuit 1.27 mm Pitch)
pins on every part: 4 V+ (power), 11 V- (power)
part A pins: 1 OUT (out), 2 IN- (in), 3 IN+ (in)
part B pins: 5 IN+ (in), 6 IN- (in), 7 OUT (out)
part C pins: 8 OUT (out), 9 IN- (in), 10 IN+ (in)
part D pins: 12 IN+ (in), 13 IN- (in), 14 OUT (out)

## MC35004AN
designator U?
General-Purpose Quad J-FET Operational Amplifier
footprint DIP14 (DIP; 14 Leads; Row Spacing 7.62 mm; Pitch 2.54 mm)
3D model DIP14 (DIP; 14 Leads; Row Spacing 7.62 mm; Pitch 2.54 mm)
pins on every part: 4 V+ (power), 11 V- (power)
part A pins: 1 OUT (out), 2 IN- (in), 3 IN+ (in)
part B pins: 5 IN+ (in), 6 IN- (in), 7 OUT (out)
part C pins: 8 OUT (out), 9 IN- (in), 10 IN+ (in)
part D pins: 12 IN+ (in), 13 IN- (in), 14 OUT (out)

## MC35004BD
designator U?
General-Purpose Quad J-FET Operational Amplifier
footprint SO14_N (SOIC, 14-Leads, Body 8.7x3.9mm, Pitch 1.27mm, IPC Medium Density)
footprint SO14_L (SOIC, 14-Leads, Body 8.7x3.9mm, Pitch 1.27mm, IPC High Density)
footprint SO14_M (SOIC, 14-Leads, Body 8.7x3.9mm, Pitch 1.27mm, IPC Low Density)
3D model SO14 (14-Pin Small Outline Integrated Circuit 1.27 mm Pitch)
pins on every part: 4 V+ (power), 11 V- (power)
part A pins: 1 OUT (out), 2 IN- (in), 3 IN+ (in)
part B pins: 5 IN+ (in), 6 IN- (in), 7 OUT (out)
part C pins: 8 OUT (out), 9 IN- (in), 10 IN+ (in)
part D pins: 12 IN+ (in), 13 IN- (in), 14 OUT (out)

## MC35004BN
designator U?
General-Purpose Quad J-FET Operational Amplifier
footprint DIP14 (DIP; 14 Leads; Row Spacing 7.62 mm; Pitch 2.54 mm)
3D model DIP14 (DIP; 14 Leads; Row Spacing 7.62 mm; Pitch 2.54 mm)
pins on every part: 4 V+ (power), 11 V- (power)
part A pins: 1 OUT (out), 2 IN- (in), 3 IN+ (in)
part B pins: 5 IN+ (in), 6 IN- (in), 7 OUT (out)
part C pins: 8 OUT (out), 9 IN- (in), 10 IN+ (in)
part D pins: 12 IN+ (in), 13 IN- (in), 14 OUT (out)

## MC35004D
designator U?
General-Purpose Quad J-FET Operational Amplifier
footprint SO14_N (SOIC, 14-Leads, Body 8.7x3.9mm, Pitch 1.27mm, IPC Medium Density)
footprint SO14_L (SOIC, 14-Leads, Body 8.7x3.9mm, Pitch 1.27mm, IPC High Density)
footprint SO14_M (SOIC, 14-Leads, Body 8.7x3.9mm, Pitch 1.27mm, IPC Low Density)
3D model SO14 (14-Pin Small Outline Integrated Circuit 1.27 mm Pitch)
pins on every part: 4 V+ (power), 11 V- (power)
part A pins: 1 OUT (out), 2 IN- (in), 3 IN+ (in)
part B pins: 5 IN+ (in), 6 IN- (in), 7 OUT (out)
part C pins: 8 OUT (out), 9 IN- (in), 10 IN+ (in)
part D pins: 12 IN+ (in), 13 IN- (in), 14 OUT (out)

## MC35004N
designator U?
General-Purpose Quad J-FET Operational Amplifier
footprint DIP14 (DIP; 14 Leads; Row Spacing 7.62 mm; Pitch 2.54 mm)
3D model DIP14 (DIP; 14 Leads; Row Spacing 7.62 mm; Pitch 2.54 mm)
pins on every part: 4 V+ (power), 11 V- (power)
part A pins: 1 OUT (out), 2 IN- (in), 3 IN+ (in)
part B pins: 5 IN+ (in), 6 IN- (in), 7 OUT (out)
part C pins: 8 OUT (out), 9 IN- (in), 10 IN+ (in)
part D pins: 12 IN+ (in), 13 IN- (in), 14 OUT (out)

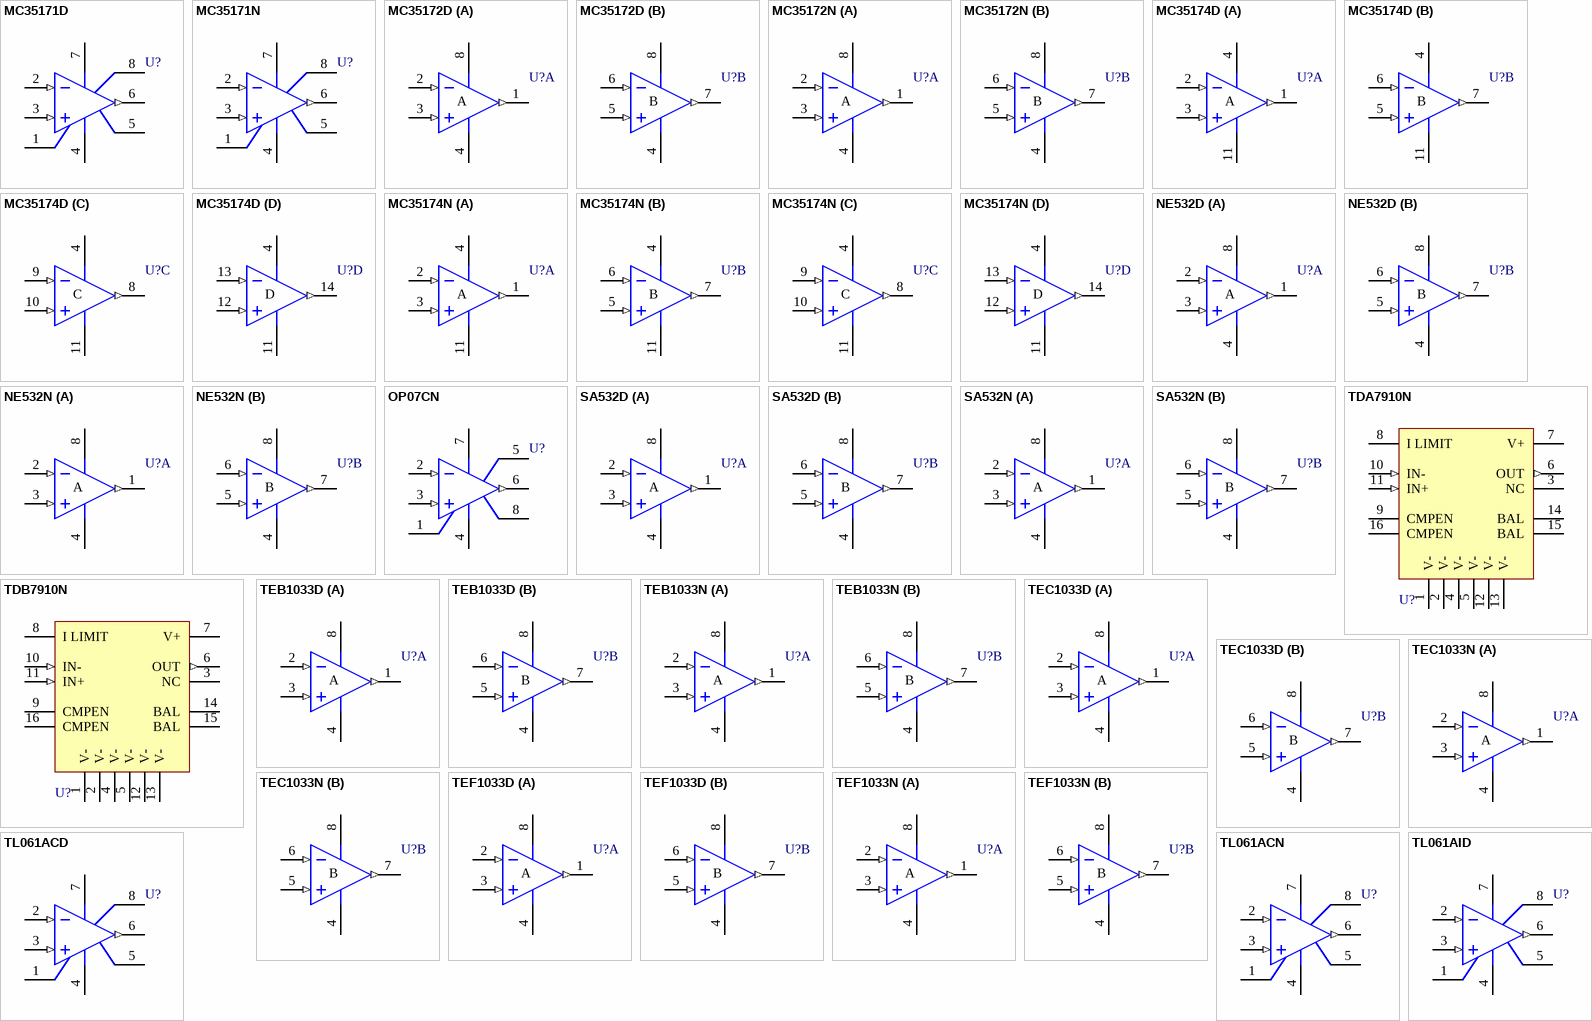
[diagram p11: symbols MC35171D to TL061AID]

## MC35171D
designator U?
Low-Power Single Bipolar Operational Amplifier
footprint SO8_N (SOIC, 8-Leads, Body 4.9x3.9mm, Pitch 1.27mm, IPC Medium Density)
footprint SO8_L (SOIC, 8-Leads, Body 4.9x3.9mm, Pitch 1.27mm, IPC High Density)
footprint SO8_M (SOIC, 8-Leads, Body 4.9x3.9mm, Pitch 1.27mm, IPC Low Density)
3D model SO8 (8-Pin Small Outline Integrated Circuit 1.27 mm Pitch)
pins: 1 OS NULL, 2 IN- (in), 3 IN+ (in), 4 V- (power), 5 OS NULL, 6 OUT (out), 7 V+ (power), 8 NC

## MC35171N
designator U?
Low-Power Single Bipolar Operational Amplifier
footprint DIP8 (DIP; 8 Leads; Row Spacing 7.62 mm; Pitch 2.54 mm)
3D model DIP8 (DIP; 8 Leads; Row Spacing 7.62 mm; Pitch 2.54 mm)
pins: 1 OS NULL, 2 IN- (in), 3 IN+ (in), 4 V- (power), 5 OS NULL, 6 OUT (out), 7 V+ (power), 8 NC

## MC35172D
designator U?
Low-Power Dual Bipolar Operational Amplifier
footprint SO8_N (SOIC, 8-Leads, Body 4.9x3.9mm, Pitch 1.27mm, IPC Medium Density)
footprint SO8_L (SOIC, 8-Leads, Body 4.9x3.9mm, Pitch 1.27mm, IPC High Density)
footprint SO8_M (SOIC, 8-Leads, Body 4.9x3.9mm, Pitch 1.27mm, IPC Low Density)
3D model SO8 (8-Pin Small Outline Integrated Circuit 1.27 mm Pitch)
pins on every part: 4 V- (power), 8 V+ (power)
part A pins: 1 OUT (out), 2 IN- (in), 3 IN+ (in)
part B pins: 5 IN+ (in), 6 IN- (in), 7 OUT (out)

## MC35172N
designator U?
Low-Power Dual Bipolar Operational Amplifier
footprint DIP8 (DIP; 8 Leads; Row Spacing 7.62 mm; Pitch 2.54 mm)
3D model DIP8 (DIP; 8 Leads; Row Spacing 7.62 mm; Pitch 2.54 mm)
pins on every part: 4 V- (power), 8 V+ (power)
part A pins: 1 OUT (out), 2 IN- (in), 3 IN+ (in)
part B pins: 5 IN+ (in), 6 IN- (in), 7 OUT (out)

## MC35174D
designator U?
Low-Power Quad Bipolar Operational Amplifier
footprint SO14_N (SOIC, 14-Leads, Body 8.7x3.9mm, Pitch 1.27mm, IPC Medium Density)
footprint SO14_L (SOIC, 14-Leads, Body 8.7x3.9mm, Pitch 1.27mm, IPC High Density)
footprint SO14_M (SOIC, 14-Leads, Body 8.7x3.9mm, Pitch 1.27mm, IPC Low Density)
3D model SO14 (14-Pin Small Outline Integrated Circuit 1.27 mm Pitch)
pins on every part: 4 V+ (power), 11 V- (power)
part A pins: 1 OUT (out), 2 IN- (in), 3 IN+ (in)
part B pins: 5 IN+ (in), 6 IN- (in), 7 OUT (out)
part C pins: 8 OUT (out), 9 IN- (in), 10 IN+ (in)
part D pins: 12 IN+ (in), 13 IN- (in), 14 OUT (out)

## MC35174N
designator U?
Low-Power Quad Bipolar Operational Amplifier
footprint DIP14 (DIP; 14 Leads; Row Spacing 7.62 mm; Pitch 2.54 mm)
3D model DIP14 (DIP; 14 Leads; Row Spacing 7.62 mm; Pitch 2.54 mm)
pins on every part: 4 V+ (power), 11 V- (power)
part A pins: 1 OUT (out), 2 IN- (in), 3 IN+ (in)
part B pins: 5 IN+ (in), 6 IN- (in), 7 OUT (out)
part C pins: 8 OUT (out), 9 IN- (in), 10 IN+ (in)
part D pins: 12 IN+ (in), 13 IN- (in), 14 OUT (out)

## NE532D
designator U?
Low-Power Dual Operational Amplifier
footprint SO8_N (SOIC, 8-Leads, Body 4.9x3.9mm, Pitch 1.27mm, IPC Medium Density)
footprint SO8_L (SOIC, 8-Leads, Body 4.9x3.9mm, Pitch 1.27mm, IPC High Density)
footprint SO8_M (SOIC, 8-Leads, Body 4.9x3.9mm, Pitch 1.27mm, IPC Low Density)
3D model SO8 (8-Pin Small Outline Integrated Circuit 1.27 mm Pitch)
pins on every part: 4 V- (power), 8 V+ (power)
part A pins: 1 OUT (out), 2 IN- (in), 3 IN+ (in)
part B pins: 5 IN+ (in), 6 IN- (in), 7 OUT (out)

## NE532N
designator U?
Low-Power Dual Operational Amplifier
footprint DIP8 (DIP; 8 Leads; Row Spacing 7.62 mm; Pitch 2.54 mm)
3D model DIP8 (DIP; 8 Leads; Row Spacing 7.62 mm; Pitch 2.54 mm)
pins on every part: 4 V- (power), 8 V+ (power)
part A pins: 1 OUT (out), 2 IN- (in), 3 IN+ (in)
part B pins: 5 IN+ (in), 6 IN- (in), 7 OUT (out)

## OP07CN
designator U?
Very Low Offset Single Bipolar Operational Amplifier; Note: Pins 5 is Not Connected
footprint DIP8 (DIP; 8 Leads; Row Spacing 7.62 mm; Pitch 2.54 mm)
3D model DIP8 (DIP; 8 Leads; Row Spacing 7.62 mm; Pitch 2.54 mm)
simulation model OP07C (SUBCKT)
pins: 1 NULL1, 2 IN- (in), 3 IN+ (in), 4 V- (power), 5 NC, 6 OUT (out), 7 V+ (power), 8 NULL2

## SA532D
designator U?
Low-Power Dual Operational Amplifier
footprint SO8_N (SOIC, 8-Leads, Body 4.9x3.9mm, Pitch 1.27mm, IPC Medium Density)
footprint SO8_L (SOIC, 8-Leads, Body 4.9x3.9mm, Pitch 1.27mm, IPC High Density)
footprint SO8_M (SOIC, 8-Leads, Body 4.9x3.9mm, Pitch 1.27mm, IPC Low Density)
3D model SO8 (8-Pin Small Outline Integrated Circuit 1.27 mm Pitch)
pins on every part: 4 V- (power), 8 V+ (power)
part A pins: 1 OUT (out), 2 IN- (in), 3 IN+ (in)
part B pins: 5 IN+ (in), 6 IN- (in), 7 OUT (out)

## SA532N
designator U?
Low-Power Dual Operational Amplifier
footprint DIP8 (DIP; 8 Leads; Row Spacing 7.62 mm; Pitch 2.54 mm)
3D model DIP8 (DIP; 8 Leads; Row Spacing 7.62 mm; Pitch 2.54 mm)
pins on every part: 4 V- (power), 8 V+ (power)
part A pins: 1 OUT (out), 2 IN- (in), 3 IN+ (in)
part B pins: 5 IN+ (in), 6 IN- (in), 7 OUT (out)

## TDA7910N
designator U?
Medium-Power Single Bipolar Operational Amplifier
footprint DIP16 (DIP; 16 Leads; Row Spacing 7.62 mm; Pitch 2.54 mm)
3D model DIP16 (DIP; 16 Leads; Row Spacing 7.62 mm; Pitch 2.54 mm)
pins: 1 V- (power), 2 V- (power), 3 NC, 4 V- (power), 5 V- (power), 6 OUT (out), 7 V+ (power), 8 I LIMIT, 9 CMPEN, 10 IN- (in), 11 IN+ (in), 12 V- (power), 13 V- (power), 14 BAL, 15 BAL, 16 CMPEN

## TDB7910N
designator U?
Medium-Power Single Bipolar Operational Amplifier
footprint DIP16 (DIP; 16 Leads; Row Spacing 7.62 mm; Pitch 2.54 mm)
3D model DIP16 (DIP; 16 Leads; Row Spacing 7.62 mm; Pitch 2.54 mm)
pins: 1 V- (power), 2 V- (power), 3 NC, 4 V- (power), 5 V- (power), 6 OUT (out), 7 V+ (power), 8 I LIMIT, 9 CMPEN, 10 IN- (in), 11 IN+ (in), 12 V- (power), 13 V- (power), 14 BAL, 15 BAL, 16 CMPEN

## TEB1033D
designator U?
Precision Dual Operational Amplifier
footprint SO8_N (SOIC, 8-Leads, Body 4.9x3.9mm, Pitch 1.27mm, IPC Medium Density)
footprint SO8_L (SOIC, 8-Leads, Body 4.9x3.9mm, Pitch 1.27mm, IPC High Density)
footprint SO8_M (SOIC, 8-Leads, Body 4.9x3.9mm, Pitch 1.27mm, IPC Low Density)
3D model SO8 (8-Pin Small Outline Integrated Circuit 1.27 mm Pitch)
pins on every part: 4 V- (power), 8 V+ (power)
part A pins: 1 OUT (out), 2 IN- (in), 3 IN+ (in)
part B pins: 5 IN+ (in), 6 IN- (in), 7 OUT (out)

## TEB1033N
designator U?
Precision Dual Operational Amplifier
footprint DIP8 (DIP; 8 Leads; Row Spacing 7.62 mm; Pitch 2.54 mm)
3D model DIP8 (DIP; 8 Leads; Row Spacing 7.62 mm; Pitch 2.54 mm)
pins on every part: 4 V- (power), 8 V+ (power)
part A pins: 1 OUT (out), 2 IN- (in), 3 IN+ (in)
part B pins: 5 IN+ (in), 6 IN- (in), 7 OUT (out)

## TEC1033D
designator U?
Precision Dual Operational Amplifier
footprint SO8_N (SOIC, 8-Leads, Body 4.9x3.9mm, Pitch 1.27mm, IPC Medium Density)
footprint SO8_L (SOIC, 8-Leads, Body 4.9x3.9mm, Pitch 1.27mm, IPC High Density)
footprint SO8_M (SOIC, 8-Leads, Body 4.9x3.9mm, Pitch 1.27mm, IPC Low Density)
3D model SO8 (8-Pin Small Outline Integrated Circuit 1.27 mm Pitch)
pins on every part: 4 V- (power), 8 V+ (power)
part A pins: 1 OUT (out), 2 IN- (in), 3 IN+ (in)
part B pins: 5 IN+ (in), 6 IN- (in), 7 OUT (out)

## TEC1033N
designator U?
Precision Dual Operational Amplifier
footprint DIP8 (DIP; 8 Leads; Row Spacing 7.62 mm; Pitch 2.54 mm)
3D model DIP8 (DIP; 8 Leads; Row Spacing 7.62 mm; Pitch 2.54 mm)
pins on every part: 4 V- (power), 8 V+ (power)
part A pins: 1 OUT (out), 2 IN- (in), 3 IN+ (in)
part B pins: 5 IN+ (in), 6 IN- (in), 7 OUT (out)

## TEF1033D
designator U?
Precision Dual Operational Amplifier
footprint SO8_N (SOIC, 8-Leads, Body 4.9x3.9mm, Pitch 1.27mm, IPC Medium Density)
footprint SO8_L (SOIC, 8-Leads, Body 4.9x3.9mm, Pitch 1.27mm, IPC High Density)
footprint SO8_M (SOIC, 8-Leads, Body 4.9x3.9mm, Pitch 1.27mm, IPC Low Density)
3D model SO8 (8-Pin Small Outline Integrated Circuit 1.27 mm Pitch)
pins on every part: 4 V- (power), 8 V+ (power)
part A pins: 1 OUT (out), 2 IN- (in), 3 IN+ (in)
part B pins: 5 IN+ (in), 6 IN- (in), 7 OUT (out)

## TEF1033N
designator U?
Precision Dual Operational Amplifier
footprint DIP8 (DIP; 8 Leads; Row Spacing 7.62 mm; Pitch 2.54 mm)
3D model DIP8 (DIP; 8 Leads; Row Spacing 7.62 mm; Pitch 2.54 mm)
pins on every part: 4 V- (power), 8 V+ (power)
part A pins: 1 OUT (out), 2 IN- (in), 3 IN+ (in)
part B pins: 5 IN+ (in), 6 IN- (in), 7 OUT (out)

## TL061ACD
designator U?
Low-Power J-FET Single Operational Amplifier
footprint SO8_N (SOIC, 8-Leads, Body 4.9x3.9mm, Pitch 1.27mm, IPC Medium Density)
footprint SO8_L (SOIC, 8-Leads, Body 4.9x3.9mm, Pitch 1.27mm, IPC High Density)
footprint SO8_M (SOIC, 8-Leads, Body 4.9x3.9mm, Pitch 1.27mm, IPC Low Density)
3D model SO8 (8-Pin Small Outline Integrated Circuit 1.27 mm Pitch)
simulation model TL061 (SUBCKT)
pins: 1 OS NULL, 2 IN- (in), 3 IN+ (in), 4 V- (power), 5 OS NULL, 6 OUT (out), 7 V+ (power), 8 NC

## TL061ACN
designator U?
Low-Power J-FET Single Operational Amplifier
footprint DIP8 (DIP; 8 Leads; Row Spacing 7.62 mm; Pitch 2.54 mm)
3D model DIP8 (DIP; 8 Leads; Row Spacing 7.62 mm; Pitch 2.54 mm)
simulation model TL061 (SUBCKT)
pins: 1 OS NULL, 2 IN- (in), 3 IN+ (in), 4 V- (power), 5 OS NULL, 6 OUT (out), 7 V+ (power), 8 NC

## TL061AID
designator U?
Low-Power J-FET Single Operational Amplifier
footprint SO8_N (SOIC, 8-Leads, Body 4.9x3.9mm, Pitch 1.27mm, IPC Medium Density)
footprint SO8_L (SOIC, 8-Leads, Body 4.9x3.9mm, Pitch 1.27mm, IPC High Density)
footprint SO8_M (SOIC, 8-Leads, Body 4.9x3.9mm, Pitch 1.27mm, IPC Low Density)
3D model SO8 (8-Pin Small Outline Integrated Circuit 1.27 mm Pitch)
simulation model TL061 (SUBCKT)
pins: 1 OS NULL, 2 IN- (in), 3 IN+ (in), 4 V- (power), 5 OS NULL, 6 OUT (out), 7 V+ (power), 8 NC

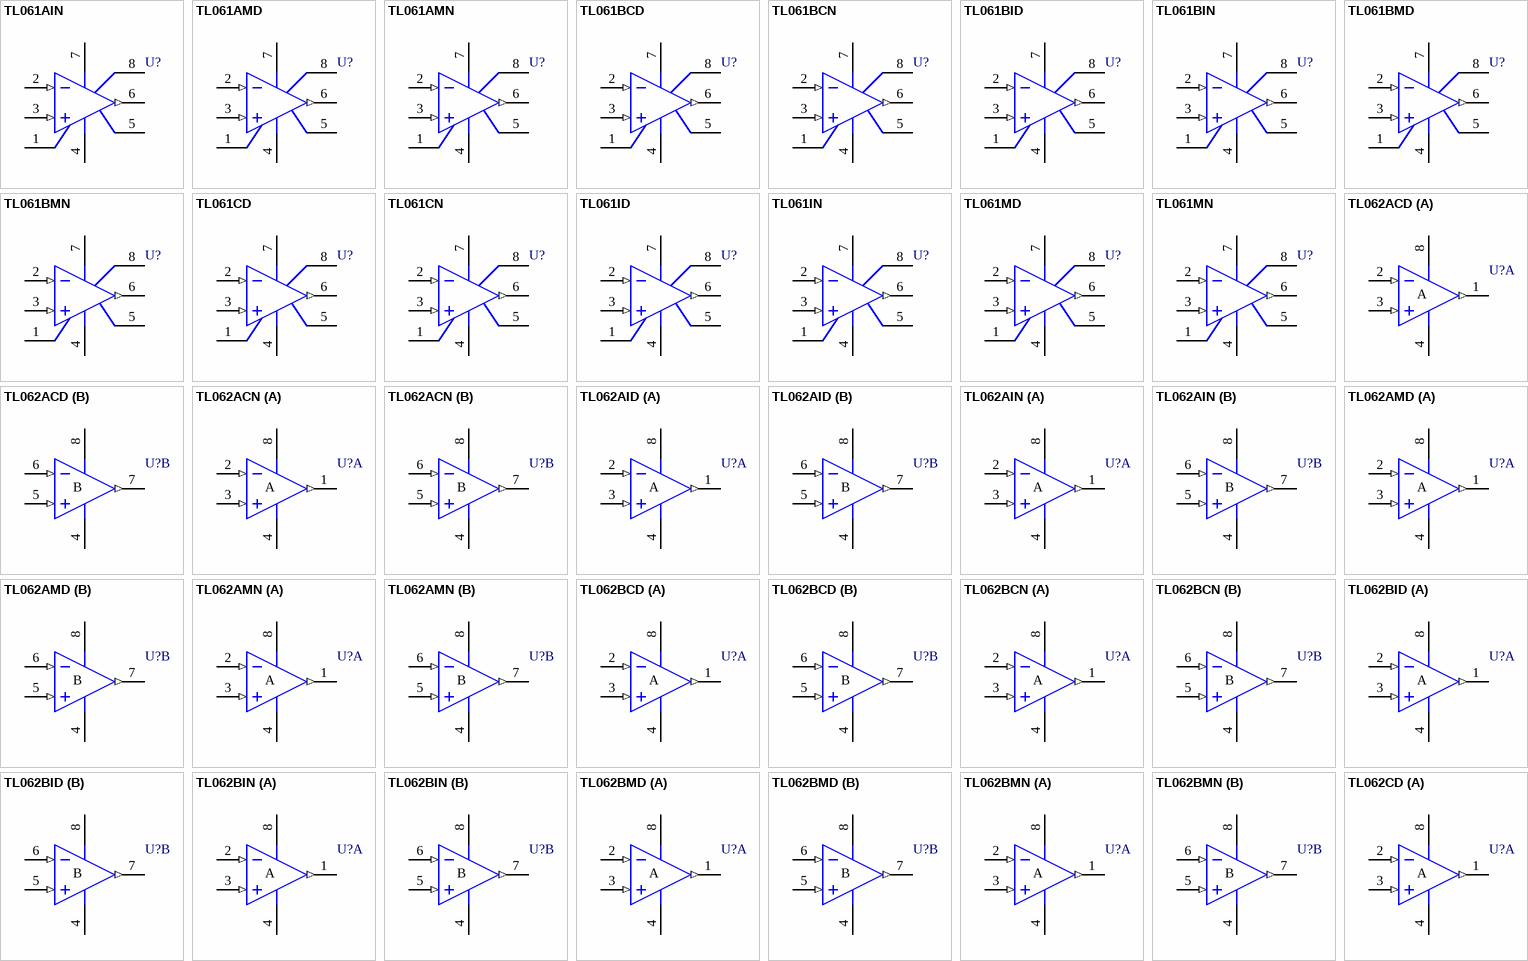
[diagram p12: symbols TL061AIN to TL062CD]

## TL061AIN
designator U?
Low-Power J-FET Single Operational Amplifier
footprint DIP8 (DIP; 8 Leads; Row Spacing 7.62 mm; Pitch 2.54 mm)
3D model DIP8 (DIP; 8 Leads; Row Spacing 7.62 mm; Pitch 2.54 mm)
simulation model TL061 (SUBCKT)
pins: 1 OS NULL, 2 IN- (in), 3 IN+ (in), 4 V- (power), 5 OS NULL, 6 OUT (out), 7 V+ (power), 8 NC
